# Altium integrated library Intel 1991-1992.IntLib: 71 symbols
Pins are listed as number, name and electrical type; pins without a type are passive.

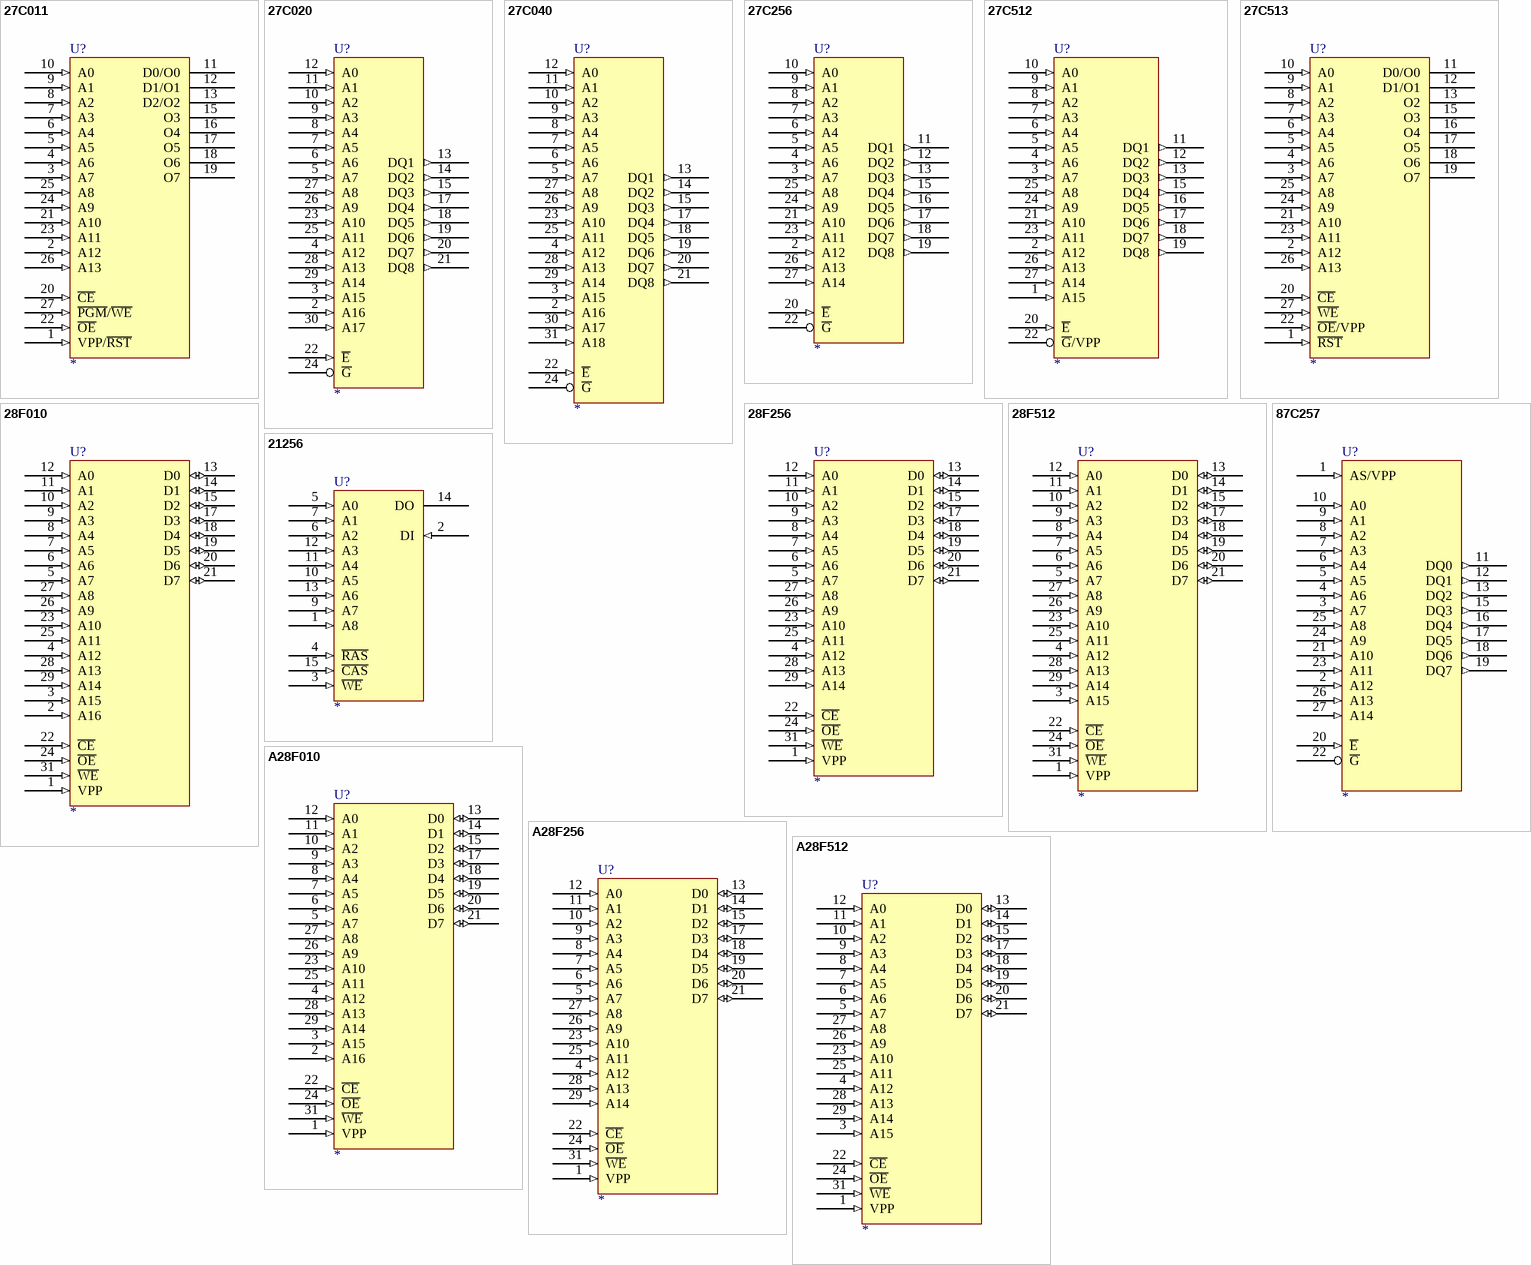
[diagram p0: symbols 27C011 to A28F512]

## 27C011
designator U?
pins: 1 VPP/~{RST} (in), 2 A12 (in), 3 A7 (in), 4 A6 (in), 5 A5 (in), 6 A4 (in), 7 A3 (in), 8 A2 (in), 9 A1 (in), 10 A0 (in), 11 D0/O0 (hiz), 12 D1/O1 (hiz), 13 D2/O2 (hiz), 14 GND (power) hidden to GND, 15 O3 (hiz), 16 O4 (hiz), 17 O5 (hiz), 18 O6 (hiz), 19 O7 (hiz), 20 ~{CE} (in), 21 A10 (in), 22 ~{OE} (in), 23 A11 (in), 24 A9 (in), 25 A8 (in), 26 A13 (in), 27 ~{PGM}/~{WE} (in), 28 VCC (power) hidden to VCC

## 27C020
designator U?
2 097 152-BIT UV ERASABLE PROGRAMMABLE READ-ONLY MEMORY
footprint DIP-32
pins: 1 VPP (power) hidden to VPP, 2 A16 (in), 3 A15 (in), 4 A12 (in), 5 A7 (in), 6 A6 (in), 7 A5 (in), 8 A4 (in), 9 A3 (in), 10 A2 (in), 11 A1 (in), 12 A0 (in), 13 DQ1 (out), 14 DQ2 (out), 15 DQ3 (out), 16 GND (power) hidden to GND, 17 DQ4 (out), 18 DQ5 (out), 19 DQ6 (out), 20 DQ7 (out), 21 DQ8 (out), 22 ~{E} (in), 23 A10 (in), 24 ~{G}, 25 A11 (in), 26 A9 (in), 27 A8 (in), 28 A13 (in), 29 A14 (in), 30 A17 (in), 32 VCC (power) hidden to VCC
1 alternate drawing of the same symbol

## 27C040
designator U?
4 194 304-BIT UV ERASABLE PROGRAMMABLE READ-ONLY MEMORY
footprint DIP-32
pins: 1 VPP (power) hidden to VPP, 2 A16 (in), 3 A15 (in), 4 A12 (in), 5 A7 (in), 6 A6 (in), 7 A5 (in), 8 A4 (in), 9 A3 (in), 10 A2 (in), 11 A1 (in), 12 A0 (in), 13 DQ1 (out), 14 DQ2 (out), 15 DQ3 (out), 16 GND (power) hidden to GND, 17 DQ4 (out), 18 DQ5 (out), 19 DQ6 (out), 20 DQ7 (out), 21 DQ8 (out), 22 ~{E} (in), 23 A10 (in), 24 ~{G}, 25 A11 (in), 26 A9 (in), 27 A8 (in), 28 A13 (in), 29 A14 (in), 30 A17 (in), 31 A18 (in), 32 VCC (power) hidden to VCC
1 alternate drawing of the same symbol

## 27C256
designator U?
262 144-BIT UV ERASABLE PROGRAMMABLE READ-ONLY MEMORY
footprint DIP-28
pins: 2 A12 (in), 3 A7 (in), 4 A6 (in), 5 A5 (in), 6 A4 (in), 7 A3 (in), 8 A2 (in), 9 A1 (in), 10 A0 (in), 11 DQ1 (out), 12 DQ2 (out), 13 DQ3 (out), 14 GND (power) hidden to GND, 15 DQ4 (out), 16 DQ5 (out), 17 DQ6 (out), 18 DQ7 (out), 19 DQ8 (out), 20 ~{E} (in), 21 A10 (in), 22 ~{G}, 23 A11 (in), 24 A9 (in), 25 A8 (in), 26 A13 (in), 27 A14 (in), 28 VCC (power) hidden to VCC
1 alternate drawing of the same symbol

## 27C512
designator U?
524 288-BIT ERASABLE UV PROGRAMMABLE READ-ONLY MEMORY
footprint DIP-28
pins: 1 A15 (in), 2 A12 (in), 3 A7 (in), 4 A6 (in), 5 A5 (in), 6 A4 (in), 7 A3 (in), 8 A2 (in), 9 A1 (in), 10 A0 (in), 11 DQ1 (out), 12 DQ2 (out), 13 DQ3 (out), 14 GND (power) hidden to GND, 15 DQ4 (out), 16 DQ5 (out), 17 DQ6 (out), 18 DQ7 (out), 19 DQ8 (out), 20 ~{E} (in), 21 A10 (in), 22 ~{G}/VPP, 23 A11 (in), 24 A9 (in), 25 A8 (in), 26 A13 (in), 27 A14 (in), 28 VCC (power) hidden to VCC
1 alternate drawing of the same symbol

## 27C513
designator U?
pins: 1 ~{RST} (in), 2 A12 (in), 3 A7 (in), 4 A6 (in), 5 A5 (in), 6 A4 (in), 7 A3 (in), 8 A2 (in), 9 A1 (in), 10 A0 (in), 11 D0/O0 (hiz), 12 D1/O1 (hiz), 13 O2 (hiz), 14 GND (power) hidden to GND, 15 O3 (hiz), 16 O4 (hiz), 17 O5 (hiz), 18 O6 (hiz), 19 O7 (hiz), 20 ~{CE} (in), 21 A10 (in), 22 ~{OE}/VPP (in), 23 A11 (in), 24 A9 (in), 25 A8 (in), 26 A13 (in), 27 ~{WE} (in), 28 VCC (power) hidden to VCC

## 28F010
designator U?
pins: 1 VPP (in), 2 A16 (in), 3 A15 (in), 4 A12 (in), 5 A7 (in), 6 A6 (in), 7 A5 (in), 8 A4 (in), 9 A3 (in), 10 A2 (in), 11 A1 (in), 12 A0 (in), 13 D0 (io), 14 D1 (io), 15 D2 (io), 16 GND (power) hidden to GND, 17 D3 (io), 18 D4 (io), 19 D5 (io), 20 D6 (io), 21 D7 (io), 22 ~{CE} (in), 23 A10 (in), 24 ~{OE} (in), 25 A11 (in), 26 A9 (in), 27 A8 (in), 28 A13 (in), 29 A14 (in), 31 ~{WE} (in), 32 VCC (power) hidden to VCC

## 28F256
designator U?
pins: 1 VPP (in), 4 A12 (in), 5 A7 (in), 6 A6 (in), 7 A5 (in), 8 A4 (in), 9 A3 (in), 10 A2 (in), 11 A1 (in), 12 A0 (in), 13 D0 (io), 14 D1 (io), 15 D2 (io), 16 VSS (power) hidden to VSS, 17 D3 (io), 18 D4 (io), 19 D5 (io), 20 D6 (io), 21 D7 (io), 22 ~{CE} (in), 23 A10 (in), 24 ~{OE} (in), 25 A11 (in), 26 A9 (in), 27 A8 (in), 28 A13 (in), 29 A14 (in), 31 ~{WE} (in), 32 VCC (power) hidden to VCC

## 28F512
designator U?
pins: 1 VPP (in), 3 A15 (in), 4 A12 (in), 5 A7 (in), 6 A6 (in), 7 A5 (in), 8 A4 (in), 9 A3 (in), 10 A2 (in), 11 A1 (in), 12 A0 (in), 13 D0 (io), 14 D1 (io), 15 D2 (io), 16 VSS (power) hidden to VSS, 17 D3 (io), 18 D4 (io), 19 D5 (io), 20 D6 (io), 21 D7 (io), 22 ~{CE} (in), 23 A10 (in), 24 ~{OE} (in), 25 A11 (in), 26 A9 (in), 27 A8 (in), 28 A13 (in), 29 A14 (in), 31 ~{WE} (in), 32 VCC (power) hidden to VCC

## 87C257
designator U?
262 144-BIT LATCHED UV ERASABLE PROGRAMMABLE READ-ONLY MEMORY
footprint DIP-28
pins: 1 AS/VPP (in), 2 A12 (in), 3 A7 (in), 4 A6 (in), 5 A5 (in), 6 A4 (in), 7 A3 (in), 8 A2 (in), 9 A1 (in), 10 A0 (in), 11 DQ0 (out), 12 DQ1 (out), 13 DQ2 (out), 14 GND (power) hidden to GND, 15 DQ3 (out), 16 DQ4 (out), 17 DQ5 (out), 18 DQ6 (out), 19 DQ7 (out), 20 ~{E} (in), 21 A10 (in), 22 ~{G}, 23 A11 (in), 24 A9 (in), 25 A8 (in), 26 A13 (in), 27 A14 (in), 28 VCC (power) hidden to VCC
1 alternate drawing of the same symbol

## 21256
designator U?
pins: 1 A8 (in), 2 DI (in), 3 ~{WE} (in), 4 ~{RAS} (in), 5 A0 (in), 6 A2 (in), 7 A1 (in), 8 VCC (power) hidden to VCC, 9 A7 (in), 10 A5 (in), 11 A4 (in), 12 A3 (in), 13 A6 (in), 14 DO (hiz), 15 ~{CAS} (in), 16 VSS (power) hidden to VSS

## A28F010
designator U?
pins: 1 VPP (in), 2 A16 (in), 3 A15 (in), 4 A12 (in), 5 A7 (in), 6 A6 (in), 7 A5 (in), 8 A4 (in), 9 A3 (in), 10 A2 (in), 11 A1 (in), 12 A0 (in), 13 D0 (io), 14 D1 (io), 15 D2 (io), 16 GND (power) hidden to GND, 17 D3 (io), 18 D4 (io), 19 D5 (io), 20 D6 (io), 21 D7 (io), 22 ~{CE} (in), 23 A10 (in), 24 ~{OE} (in), 25 A11 (in), 26 A9 (in), 27 A8 (in), 28 A13 (in), 29 A14 (in), 31 ~{WE} (in), 32 VCC (power) hidden to VCC

## A28F256
designator U?
pins: 1 VPP (in), 4 A12 (in), 5 A7 (in), 6 A6 (in), 7 A5 (in), 8 A4 (in), 9 A3 (in), 10 A2 (in), 11 A1 (in), 12 A0 (in), 13 D0 (io), 14 D1 (io), 15 D2 (io), 16 VSS (power) hidden to VSS, 17 D3 (io), 18 D4 (io), 19 D5 (io), 20 D6 (io), 21 D7 (io), 22 ~{CE} (in), 23 A10 (in), 24 ~{OE} (in), 25 A11 (in), 26 A9 (in), 27 A8 (in), 28 A13 (in), 29 A14 (in), 31 ~{WE} (in), 32 VCC (power) hidden to VCC

## A28F512
designator U?
pins: 1 VPP (in), 3 A15 (in), 4 A12 (in), 5 A7 (in), 6 A6 (in), 7 A5 (in), 8 A4 (in), 9 A3 (in), 10 A2 (in), 11 A1 (in), 12 A0 (in), 13 D0 (io), 14 D1 (io), 15 D2 (io), 16 VSS (power) hidden to VSS, 17 D3 (io), 18 D4 (io), 19 D5 (io), 20 D6 (io), 21 D7 (io), 22 ~{CE} (in), 23 A10 (in), 24 ~{OE} (in), 25 A11 (in), 26 A9 (in), 27 A8 (in), 28 A13 (in), 29 A14 (in), 31 ~{WE} (in), 32 VCC (power) hidden to VCC


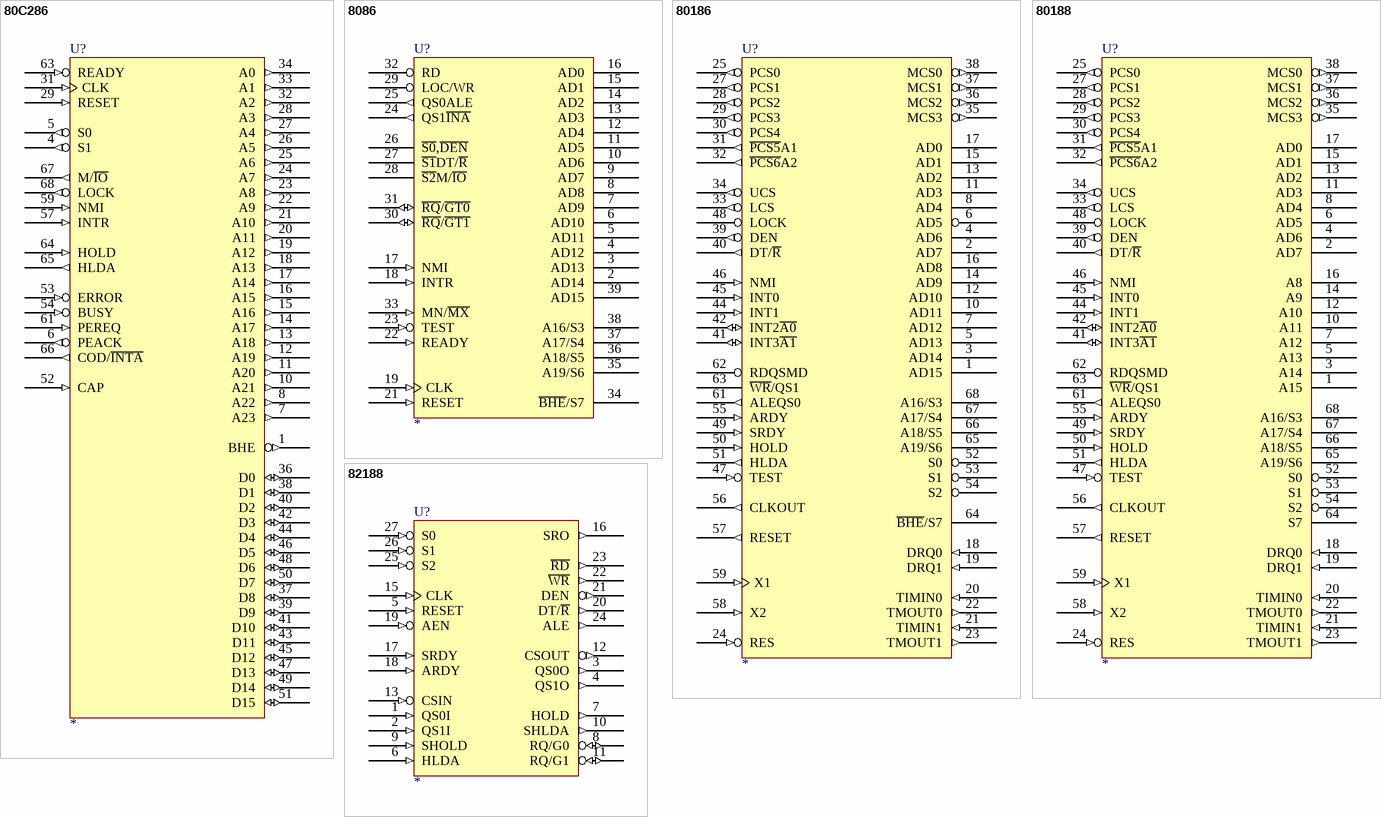
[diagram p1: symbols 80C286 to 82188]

## 80C286
designator U?
pins: 1 BHE (out), 4 S1 (out), 5 S0 (out), 6 PEACK (out), 7 A23 (out), 8 A22 (out), 9 VSS (power) hidden to VSS, 10 A21 (out), 11 A20 (out), 12 A19 (out), 13 A18 (out), 14 A17 (out), 15 A16 (out), 16 A15 (out), 17 A14 (out), 18 A13 (out), 19 A12 (out), 20 A11 (out), 21 A10 (out), 22 A9 (out), 23 A8 (out), 24 A7 (out), 25 A6 (out), 26 A5 (out), 27 A4 (out), 28 A3 (out), 29 RESET (in), 30 VCC (power) hidden to VCC, 31 CLK (in), 32 A2 (out), 33 A1 (out), 34 A0 (out), 35 VSS (power) hidden to VSS, 36 D0 (io), 37 D8 (io), 38 D1 (io), 39 D9 (io), 40 D2 (io), 41 D10 (io), 42 D3 (io), 43 D11 (io), 44 D4 (io), 45 D12 (io), 46 D5 (io), 47 D13 (io), 48 D6 (io), 49 D14 (io), 50 D7 (io), 51 D15 (io), 52 CAP (in), 53 ERROR (in), 54 BUSY (in), 57 INTR (in), 59 NMI (in), 60 VSS (power) hidden to VSS, 61 PEREQ (in), 62 VCC (power) hidden to VCC, 63 READY (in), 64 HOLD (in), 65 HLDA (out), 66 COD/~{INTA} (out), 67 M/~{IO} (out), 68 LOCK (out)

## 8086
designator U?
footprint DIP-40
pins: 1 GND (power) hidden to GND, 2 AD14 (hiz), 3 AD13 (hiz), 4 AD12 (hiz), 5 AD11 (hiz), 6 AD10 (hiz), 7 AD9 (hiz), 8 AD8 (hiz), 9 AD7 (hiz), 10 AD6 (hiz), 11 AD5 (hiz), 12 AD4 (hiz), 13 AD3 (hiz), 14 AD2 (hiz), 15 AD1 (hiz), 16 AD0 (hiz), 17 NMI (in), 18 INTR (in), 19 CLK (in), 20 GND (power) hidden to GND, 21 RESET (in), 22 READY (in), 23 TEST (in), 24 QS1~{INA} (out), 25 QS0ALE (out), 26 ~{S0},~{DEN} (hiz), 27 ~{S1}DT/~{R} (hiz), 28 ~{S2}M/~{IO} (hiz), 29 LOC/WR (hiz), 30 ~{RQ}/~{GT1} (io), 31 ~{RQ}/~{GT0} (io), 32 RD (hiz), 33 MN/~{MX} (in), 34 ~{BHE}/S7 (hiz), 35 A19/S6 (hiz), 36 A18/S5 (hiz), 37 A17/S4 (hiz), 38 A16/S3 (hiz), 39 AD15 (hiz), 40 VCC (power) hidden to VCC

## 80186
designator U?
footprint JEDECA-68
pins: 1 AD15 (hiz), 2 AD7 (hiz), 3 AD14 (hiz), 4 AD6 (hiz), 5 AD13 (hiz), 6 AD5 (hiz), 7 AD12 (hiz), 8 AD4 (hiz), 9 VCC (power) hidden to VCC, 10 AD11 (hiz), 11 AD3 (hiz), 12 AD10 (hiz), 13 AD2 (hiz), 14 AD9 (hiz), 15 AD1 (hiz), 16 AD8 (hiz), 17 AD0 (hiz), 18 DRQ0 (in), 19 DRQ1 (in), 20 TIMIN0 (in), 21 TIMIN1 (in), 22 TMOUT0 (out), 23 TMOUT1 (out), 24 RES (in), 25 PCS0 (out), 26 GND (power) hidden to GND, 27 PCS1 (out), 28 PCS2 (out), 29 PCS3 (out), 30 PCS4 (out), 31 ~{PCS5}A1 (out), 32 ~{PCS6}A2 (out), 33 LCS (out), 34 UCS (out), 35 MCS3 (out), 36 MCS2 (out), 37 MCS1 (out), 38 MCS0 (out), 39 DEN (out), 40 DT/~{R} (out), 41 INT3~{A1} (io), 42 INT2~{A0} (io), 43 VCC (power) hidden to VCC, 44 INT1 (in), 45 INT0 (in), 46 NMI (in), 47 TEST (in), 48 LOCK (hiz), 49 SRDY (in), 50 HOLD (in), 51 HLDA (out), 52 S0 (hiz), 53 S1 (hiz), 54 S2 (hiz), 55 ARDY (in), 56 CLKOUT (out), 57 RESET (out), 58 X2 (in), 59 X1 (in), 60 GND (power) hidden to GND, 61 ALEQS0 (out), 62 RDQSMD (hiz), 63 ~{WR}/QS1 (hiz), 64 ~{BHE}/S7 (hiz), 65 A19/S6 (hiz), 66 A18/S5 (hiz), 67 A17/S4 (hiz), 68 A16/S3 (hiz)

## 80188
designator U?
footprint JEDECA-68
pins: 1 A15 (hiz), 2 AD7 (hiz), 3 A14 (hiz), 4 AD6 (hiz), 5 A13 (hiz), 6 AD5 (hiz), 7 A12 (hiz), 8 AD4 (hiz), 9 VCC (power) hidden to VCC, 10 A11 (hiz), 11 AD3 (hiz), 12 A10 (hiz), 13 AD2 (hiz), 14 A9 (hiz), 15 AD1 (hiz), 16 A8 (hiz), 17 AD0 (hiz), 18 DRQ0 (in), 19 DRQ1 (in), 20 TIMIN0 (in), 21 TIMIN1 (in), 22 TMOUT0 (out), 23 TMOUT1 (out), 24 RES (in), 25 PCS0 (out), 26 GND (power) hidden to GND, 27 PCS1 (out), 28 PCS2 (out), 29 PCS3 (out), 30 PCS4 (out), 31 ~{PCS5}A1 (out), 32 ~{PCS6}A2 (out), 33 LCS (out), 34 UCS (out), 35 MCS3 (out), 36 MCS2 (out), 37 MCS1 (out), 38 MCS0 (out), 39 DEN (out), 40 DT/~{R} (out), 41 INT3~{A1} (io), 42 INT2~{A0} (io), 43 VCC (power) hidden to VCC, 44 INT1 (in), 45 INT0 (in), 46 NMI (in), 47 TEST (in), 48 LOCK (hiz), 49 SRDY (in), 50 HOLD (in), 51 HLDA (out), 52 S0 (hiz), 53 S1 (hiz), 54 S2 (hiz), 55 ARDY (in), 56 CLKOUT (out), 57 RESET (out), 58 X2 (in), 59 X1 (in), 60 GND (power) hidden to GND, 61 ALEQS0 (out), 62 RDQSMD (hiz), 63 ~{WR}/QS1 (hiz), 64 S7 (hiz), 65 A19/S6 (hiz), 66 A18/S5 (hiz), 67 A17/S4 (hiz), 68 A16/S3 (hiz)

## 82188
designator U?
pins: 1 QS0I (in), 2 QS1I (in), 3 QS0O (out), 4 QS1O (out), 5 RESET (in), 6 HLDA (in), 7 HOLD (out), 8 RQ/G0 (io), 9 SHOLD (in), 10 SHLDA (out), 11 RQ/G1 (io), 12 CSOUT (out), 13 CSIN (in), 14 VSS (power) hidden to VSS, 15 CLK (in), 16 SRO (out), 17 SRDY (in), 18 ARDY (in), 19 AEN (in), 20 DT/~{R} (out), 21 DEN (out), 22 ~{WR} (out), 23 ~{RD} (out), 24 ALE (out), 25 S2 (in), 26 S1 (in), 27 S0 (in), 28 VCC (power) hidden to VCC


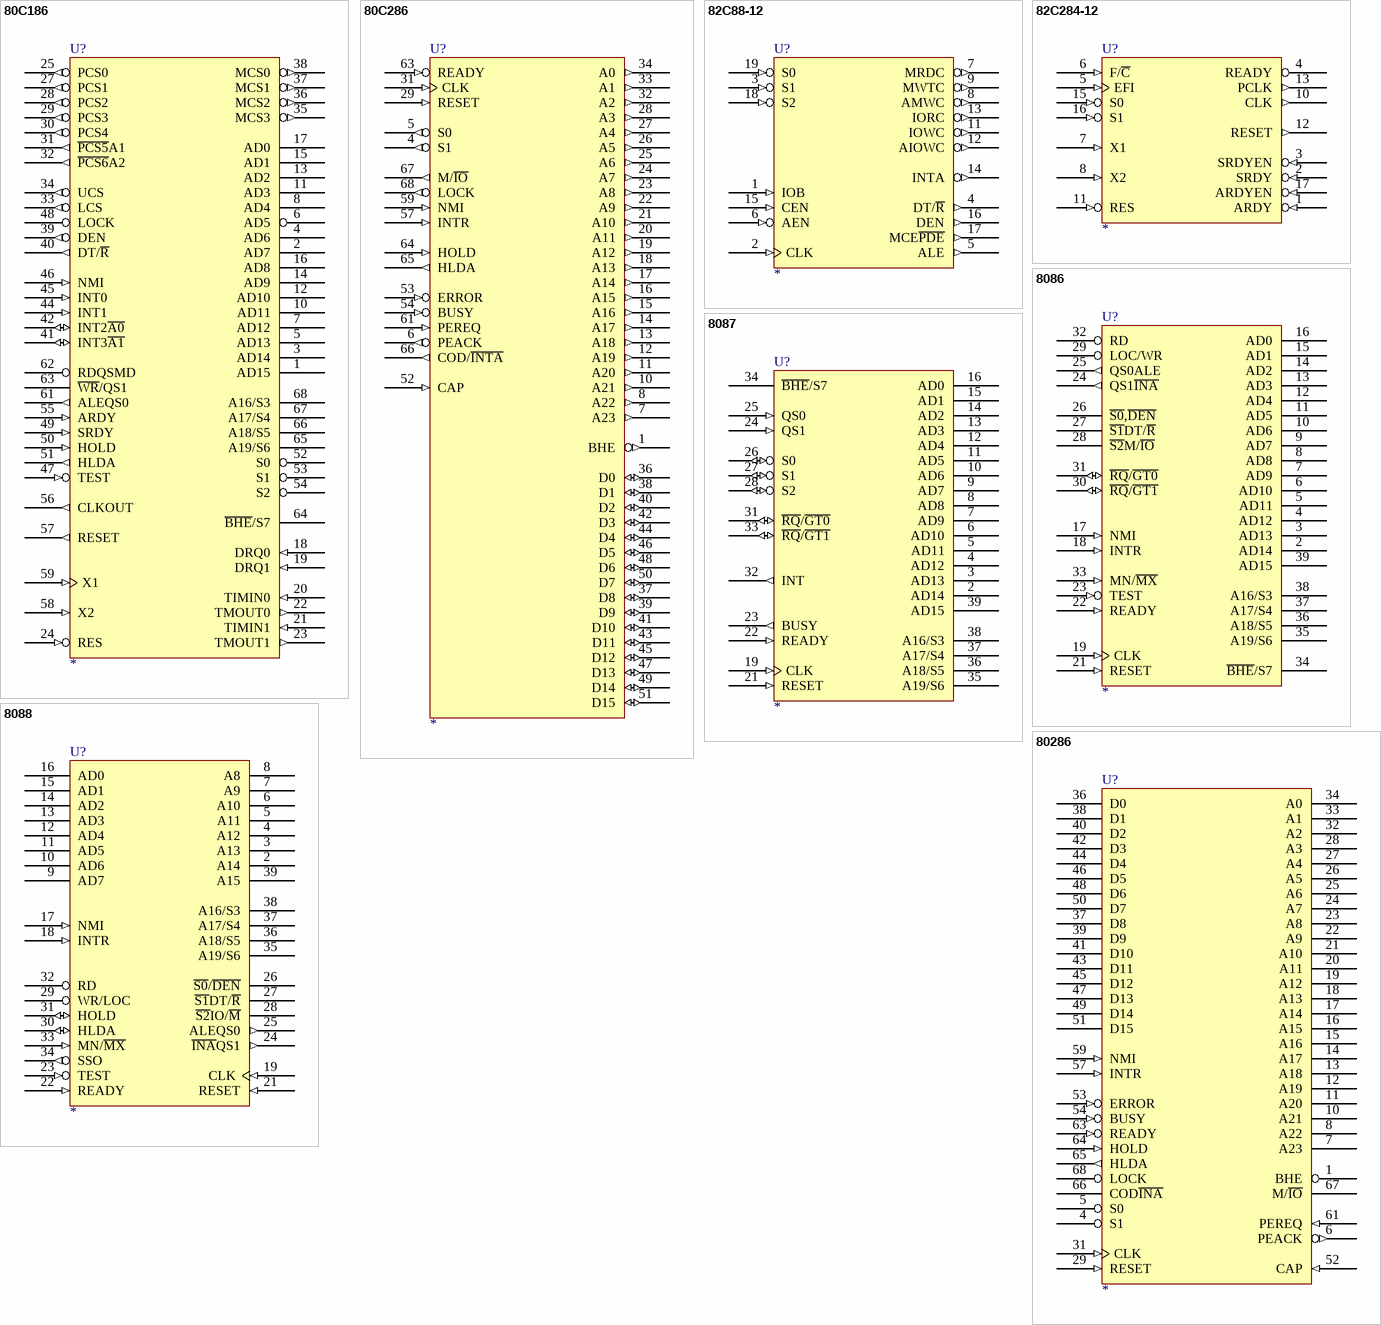
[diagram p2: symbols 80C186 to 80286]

## 80C186
designator U?
footprint JEDECA-68
pins: 1 AD15 (hiz), 2 AD7 (hiz), 3 AD14 (hiz), 4 AD6 (hiz), 5 AD13 (hiz), 6 AD5 (hiz), 7 AD12 (hiz), 8 AD4 (hiz), 9 VCC (power) hidden to VCC, 10 AD11 (hiz), 11 AD3 (hiz), 12 AD10 (hiz), 13 AD2 (hiz), 14 AD9 (hiz), 15 AD1 (hiz), 16 AD8 (hiz), 17 AD0 (hiz), 18 DRQ0 (in), 19 DRQ1 (in), 20 TIMIN0 (in), 21 TIMIN1 (in), 22 TMOUT0 (out), 23 TMOUT1 (out), 24 RES (in), 25 PCS0 (out), 26 GND (power) hidden to GND, 27 PCS1 (out), 28 PCS2 (out), 29 PCS3 (out), 30 PCS4 (out), 31 ~{PCS5}A1 (out), 32 ~{PCS6}A2 (out), 33 LCS (out), 34 UCS (out), 35 MCS3 (out), 36 MCS2 (out), 37 MCS1 (out), 38 MCS0 (out), 39 DEN (out), 40 DT/~{R} (out), 41 INT3~{A1} (io), 42 INT2~{A0} (io), 43 VCC (power) hidden to VCC, 44 INT1 (in), 45 INT0 (in), 46 NMI (in), 47 TEST (in), 48 LOCK (hiz), 49 SRDY (in), 50 HOLD (in), 51 HLDA (out), 52 S0 (hiz), 53 S1 (hiz), 54 S2 (hiz), 55 ARDY (in), 56 CLKOUT (out), 57 RESET (out), 58 X2 (in), 59 X1 (in), 60 GND (power) hidden to GND, 61 ALEQS0 (out), 62 RDQSMD (hiz), 63 ~{WR}/QS1 (hiz), 64 ~{BHE}/S7 (hiz), 65 A19/S6 (hiz), 66 A18/S5 (hiz), 67 A17/S4 (hiz), 68 A16/S3 (hiz)

## 80C286
designator U?
pins: 1 BHE (out), 4 S1 (out), 5 S0 (out), 6 PEACK (out), 7 A23 (out), 8 A22 (out), 9 VSS (power) hidden to VSS, 10 A21 (out), 11 A20 (out), 12 A19 (out), 13 A18 (out), 14 A17 (out), 15 A16 (out), 16 A15 (out), 17 A14 (out), 18 A13 (out), 19 A12 (out), 20 A11 (out), 21 A10 (out), 22 A9 (out), 23 A8 (out), 24 A7 (out), 25 A6 (out), 26 A5 (out), 27 A4 (out), 28 A3 (out), 29 RESET (in), 30 VCC (power) hidden to VCC, 31 CLK (in), 32 A2 (out), 33 A1 (out), 34 A0 (out), 35 VSS (power) hidden to VSS, 36 D0 (io), 37 D8 (io), 38 D1 (io), 39 D9 (io), 40 D2 (io), 41 D10 (io), 42 D3 (io), 43 D11 (io), 44 D4 (io), 45 D12 (io), 46 D5 (io), 47 D13 (io), 48 D6 (io), 49 D14 (io), 50 D7 (io), 51 D15 (io), 52 CAP (in), 53 ERROR (in), 54 BUSY (in), 57 INTR (in), 59 NMI (in), 60 VSS (power) hidden to VSS, 61 PEREQ (in), 62 VCC (power) hidden to VCC, 63 READY (in), 64 HOLD (in), 65 HLDA (out), 66 COD/~{INTA} (out), 67 M/~{IO} (out), 68 LOCK (out)

## 82C88-12
designator U?
footprint DIP-20
pins: 1 IOB (in), 2 CLK (in), 3 S1 (in), 4 DT/~{R} (out), 5 ALE (out), 6 AEN (in), 7 MRDC (out), 8 AMWC (out), 9 MWTC (out), 10 GND (power) hidden to GND, 11 IOWC (out), 12 AIOWC (out), 13 IORC (out), 14 INTA (out), 15 CEN (in), 16 DEN (out), 17 MCE~{PDE} (out), 18 S2 (in), 19 S0 (in), 20 VCC (power) hidden to VCC

## 82C284-12
designator U?
footprint DIP-18
pins: 1 ARDY (in), 2 SRDY (in), 3 SRDYEN (in), 4 READY (oc), 5 EFI (in), 6 F/~{C} (in), 7 X1 (in), 8 X2 (in), 9 GND (power) hidden to GND, 10 CLK (out), 11 RES (in), 12 RESET (out), 13 PCLK (out), 15 S0 (in), 16 S1 (in), 17 ARDYEN (in), 18 VCC (power) hidden to VCC

## 8086
designator U?
footprint DIP-40
pins: 1 GND (power) hidden to GND, 2 AD14 (hiz), 3 AD13 (hiz), 4 AD12 (hiz), 5 AD11 (hiz), 6 AD10 (hiz), 7 AD9 (hiz), 8 AD8 (hiz), 9 AD7 (hiz), 10 AD6 (hiz), 11 AD5 (hiz), 12 AD4 (hiz), 13 AD3 (hiz), 14 AD2 (hiz), 15 AD1 (hiz), 16 AD0 (hiz), 17 NMI (in), 18 INTR (in), 19 CLK (in), 20 GND (power) hidden to GND, 21 RESET (in), 22 READY (in), 23 TEST (in), 24 QS1~{INA} (out), 25 QS0ALE (out), 26 ~{S0},~{DEN} (hiz), 27 ~{S1}DT/~{R} (hiz), 28 ~{S2}M/~{IO} (hiz), 29 LOC/WR (hiz), 30 ~{RQ}/~{GT1} (io), 31 ~{RQ}/~{GT0} (io), 32 RD (hiz), 33 MN/~{MX} (in), 34 ~{BHE}/S7 (hiz), 35 A19/S6 (hiz), 36 A18/S5 (hiz), 37 A17/S4 (hiz), 38 A16/S3 (hiz), 39 AD15 (hiz), 40 VCC (power) hidden to VCC

## 8087
designator U?
footprint DIP-40
pins: 1 GND (power) hidden to GND, 2 AD14 (hiz), 3 AD13 (hiz), 4 AD12 (hiz), 5 AD11 (hiz), 6 AD10 (hiz), 7 AD9 (hiz), 8 AD8 (hiz), 9 AD7 (hiz), 10 AD6 (hiz), 11 AD5 (hiz), 12 AD4 (hiz), 13 AD3 (hiz), 14 AD2 (hiz), 15 AD1 (hiz), 16 AD0 (hiz), 19 CLK (in), 20 GND (power) hidden to GND, 21 RESET (in), 22 READY (in), 23 BUSY (out), 24 QS1 (in), 25 QS0 (in), 26 S0 (io), 27 S1 (io), 28 S2 (io), 31 ~{RQ}/~{GT0} (io), 32 INT (out), 33 ~{RQ}/~{GT1} (io), 34 ~{BHE}/S7 (hiz), 35 A19/S6 (hiz), 36 A18/S5 (hiz), 37 A17/S4 (hiz), 38 A16/S3 (hiz), 39 AD15 (hiz), 40 VCC (power) hidden to VCC

## 8088
designator U?
footprint DIP-40
pins: 1 GND (power) hidden to GND, 2 A14 (hiz), 3 A13 (hiz), 4 A12 (hiz), 5 A11 (hiz), 6 A10 (hiz), 7 A9 (hiz), 8 A8 (hiz), 9 AD7 (hiz), 10 AD6 (hiz), 11 AD5 (hiz), 12 AD4 (hiz), 13 AD3 (hiz), 14 AD2 (hiz), 15 AD1 (hiz), 16 AD0 (hiz), 17 NMI (in), 18 INTR (in), 19 CLK (in), 20 GND (power) hidden to GND, 21 RESET (in), 22 READY (in), 23 TEST (in), 24 ~{INA}QS1 (out), 25 ALEQS0 (out), 26 ~{S0}/~{DEN} (hiz), 27 ~{S1}DT/~{R} (hiz), 28 ~{S2}IO/~{M} (hiz), 29 WR/LOC (hiz), 30 HLDA (io), 31 HOLD (io), 32 RD (hiz), 33 MN/~{MX} (in), 34 SSO (out), 35 A19/S6 (hiz), 36 A18/S5 (hiz), 37 A17/S4 (hiz), 38 A16/S3 (hiz), 39 A15 (hiz), 40 VCC (power) hidden to VCC

## 80286
designator U?
footprint JEDECA-68
pins: 1 BHE (hiz), 4 S1 (hiz), 5 S0 (hiz), 6 PEACK (out), 7 A23 (hiz), 8 A22 (hiz), 9 GND (power) hidden to GND, 10 A21 (hiz), 11 A20 (hiz), 12 A19 (hiz), 13 A18 (hiz), 14 A17 (hiz), 15 A16 (hiz), 16 A15 (hiz), 17 A14 (hiz), 18 A13 (hiz), 19 A12 (hiz), 20 A11 (hiz), 21 A10 (hiz), 22 A9 (hiz), 23 A8 (hiz), 24 A7 (hiz), 25 A6 (hiz), 26 A5 (hiz), 27 A4 (hiz), 28 A3 (hiz), 29 RESET (in), 30 VCC (power) hidden to VCC, 31 CLK (in), 32 A2 (hiz), 33 A1 (hiz), 34 A0 (hiz), 35 GND (power) hidden to GND, 36 D0 (hiz), 37 D8 (hiz), 38 D1 (hiz), 39 D9 (hiz), 40 D2 (hiz), 41 D10 (hiz), 42 D3 (hiz), 43 D11 (hiz), 44 D4 (hiz), 45 D12 (hiz), 46 D5 (hiz), 47 D13 (hiz), 48 D6 (hiz), 49 D14 (hiz), 50 D7 (hiz), 51 D15 (hiz), 52 CAP (in), 53 ERROR (in), 54 BUSY (in), 57 INTR (in), 59 NMI (in), 60 GND (power) hidden to GND, 61 PEREQ (in), 62 VCC (power) hidden to VCC, 63 READY (in), 64 HOLD (in), 65 HLDA (out), 66 COD~{INA} (hiz), 67 M/~{IO} (hiz), 68 LOCK (hiz)


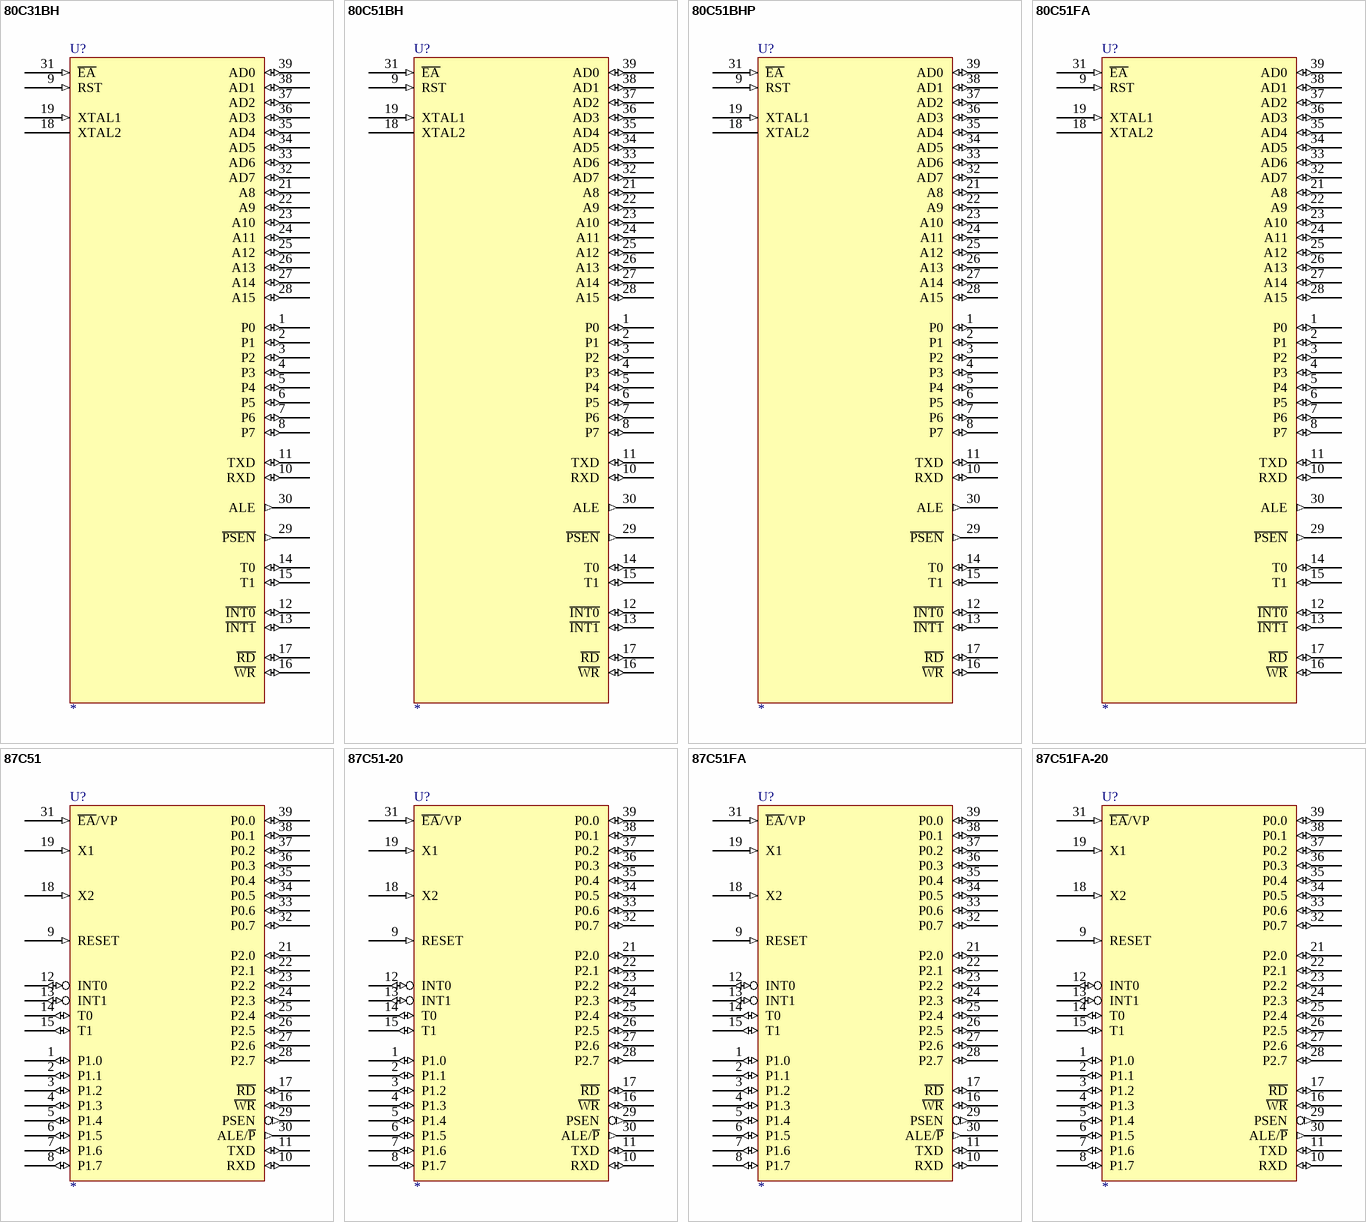
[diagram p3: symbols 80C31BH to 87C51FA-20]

## 80C31BH
designator U?
pins: 1 P0 (io), 2 P1 (io), 3 P2 (io), 4 P3 (io), 5 P4 (io), 6 P5 (io), 7 P6 (io), 8 P7 (io), 9 RST (in), 10 RXD (io), 11 TXD (io), 12 ~{INT0} (io), 13 ~{INT1} (io), 14 T0 (io), 15 T1 (io), 16 ~{WR} (io), 17 ~{RD} (io), 18 XTAL2, 19 XTAL1 (in), 20 VSS (power) hidden to VSS, 21 A8 (io), 22 A9 (io), 23 A10 (io), 24 A11 (io), 25 A12 (io), 26 A13 (io), 27 A14 (io), 28 A15 (io), 29 ~{PSEN} (out), 30 ALE (out), 31 ~{EA} (in), 32 AD7 (io), 33 AD6 (io), 34 AD5 (io), 35 AD4 (io), 36 AD3 (io), 37 AD2 (io), 38 AD1 (io), 39 AD0 (io), 40 VCC (power) hidden to VCC

## 80C51BH
designator U?
pins: 1 P0 (io), 2 P1 (io), 3 P2 (io), 4 P3 (io), 5 P4 (io), 6 P5 (io), 7 P6 (io), 8 P7 (io), 9 RST (in), 10 RXD (io), 11 TXD (io), 12 ~{INT0} (io), 13 ~{INT1} (io), 14 T0 (io), 15 T1 (io), 16 ~{WR} (io), 17 ~{RD} (io), 18 XTAL2, 19 XTAL1 (in), 20 VSS (power) hidden to VSS, 21 A8 (io), 22 A9 (io), 23 A10 (io), 24 A11 (io), 25 A12 (io), 26 A13 (io), 27 A14 (io), 28 A15 (io), 29 ~{PSEN} (out), 30 ALE (out), 31 ~{EA} (in), 32 AD7 (io), 33 AD6 (io), 34 AD5 (io), 35 AD4 (io), 36 AD3 (io), 37 AD2 (io), 38 AD1 (io), 39 AD0 (io), 40 VCC (power) hidden to VCC

## 80C51BHP
designator U?
pins: 1 P0 (io), 2 P1 (io), 3 P2 (io), 4 P3 (io), 5 P4 (io), 6 P5 (io), 7 P6 (io), 8 P7 (io), 9 RST (in), 10 RXD (io), 11 TXD (io), 12 ~{INT0} (io), 13 ~{INT1} (io), 14 T0 (io), 15 T1 (io), 16 ~{WR} (io), 17 ~{RD} (io), 18 XTAL2, 19 XTAL1 (in), 20 VSS (power) hidden to VSS, 21 A8 (io), 22 A9 (io), 23 A10 (io), 24 A11 (io), 25 A12 (io), 26 A13 (io), 27 A14 (io), 28 A15 (io), 29 ~{PSEN} (out), 30 ALE (out), 31 ~{EA} (in), 32 AD7 (io), 33 AD6 (io), 34 AD5 (io), 35 AD4 (io), 36 AD3 (io), 37 AD2 (io), 38 AD1 (io), 39 AD0 (io), 40 VCC (power) hidden to VCC

## 80C51FA
designator U?
pins: 1 P0 (io), 2 P1 (io), 3 P2 (io), 4 P3 (io), 5 P4 (io), 6 P5 (io), 7 P6 (io), 8 P7 (io), 9 RST (in), 10 RXD (io), 11 TXD (io), 12 ~{INT0} (io), 13 ~{INT1} (io), 14 T0 (io), 15 T1 (io), 16 ~{WR} (io), 17 ~{RD} (io), 18 XTAL2, 19 XTAL1 (in), 20 VSS (power) hidden to VSS, 21 A8 (io), 22 A9 (io), 23 A10 (io), 24 A11 (io), 25 A12 (io), 26 A13 (io), 27 A14 (io), 28 A15 (io), 29 ~{PSEN} (out), 30 ALE (out), 31 ~{EA} (in), 32 AD7 (io), 33 AD6 (io), 34 AD5 (io), 35 AD4 (io), 36 AD3 (io), 37 AD2 (io), 38 AD1 (io), 39 AD0 (io), 40 VCC (power) hidden to VCC

## 87C51
designator U?
pins: 1 P1.0 (io), 2 P1.1 (io), 3 P1.2 (io), 4 P1.3 (io), 5 P1.4 (io), 6 P1.5 (io), 7 P1.6 (io), 8 P1.7 (io), 9 RESET (in), 10 RXD (io), 11 TXD (io), 12 INT0 (io), 13 INT1 (io), 14 T0 (io), 15 T1 (io), 16 ~{WR} (io), 17 ~{RD} (io), 18 X2 (in), 19 X1 (in), 20 VSS (power) hidden to VSS, 21 P2.0 (io), 22 P2.1 (io), 23 P2.2 (io), 24 P2.3 (io), 25 P2.4 (io), 26 P2.5 (io), 27 P2.6 (io), 28 P2.7 (io), 29 PSEN (out), 30 ALE/~{P} (out), 31 ~{EA}/VP (in), 32 P0.7 (io), 33 P0.6 (io), 34 P0.5 (io), 35 P0.4 (io), 36 P0.3 (io), 37 P0.2 (io), 38 P0.1 (io), 39 P0.0 (io), 40 VCC (power) hidden to VCC

## 87C51-20
designator U?
pins: 1 P1.0 (io), 2 P1.1 (io), 3 P1.2 (io), 4 P1.3 (io), 5 P1.4 (io), 6 P1.5 (io), 7 P1.6 (io), 8 P1.7 (io), 9 RESET (in), 10 RXD (io), 11 TXD (io), 12 INT0 (io), 13 INT1 (io), 14 T0 (io), 15 T1 (io), 16 ~{WR} (io), 17 ~{RD} (io), 18 X2 (in), 19 X1 (in), 20 VSS (power) hidden to VSS, 21 P2.0 (io), 22 P2.1 (io), 23 P2.2 (io), 24 P2.3 (io), 25 P2.4 (io), 26 P2.5 (io), 27 P2.6 (io), 28 P2.7 (io), 29 PSEN (out), 30 ALE/~{P} (out), 31 ~{EA}/VP (in), 32 P0.7 (io), 33 P0.6 (io), 34 P0.5 (io), 35 P0.4 (io), 36 P0.3 (io), 37 P0.2 (io), 38 P0.1 (io), 39 P0.0 (io), 40 VCC (power) hidden to VCC

## 87C51FA
designator U?
pins: 1 P1.0 (io), 2 P1.1 (io), 3 P1.2 (io), 4 P1.3 (io), 5 P1.4 (io), 6 P1.5 (io), 7 P1.6 (io), 8 P1.7 (io), 9 RESET (in), 10 RXD (io), 11 TXD (io), 12 INT0 (io), 13 INT1 (io), 14 T0 (io), 15 T1 (io), 16 ~{WR} (io), 17 ~{RD} (io), 18 X2 (in), 19 X1 (in), 20 VSS (power) hidden to VSS, 21 P2.0 (io), 22 P2.1 (io), 23 P2.2 (io), 24 P2.3 (io), 25 P2.4 (io), 26 P2.5 (io), 27 P2.6 (io), 28 P2.7 (io), 29 PSEN (out), 30 ALE/~{P} (out), 31 ~{EA}/VP (in), 32 P0.7 (io), 33 P0.6 (io), 34 P0.5 (io), 35 P0.4 (io), 36 P0.3 (io), 37 P0.2 (io), 38 P0.1 (io), 39 P0.0 (io), 40 VCC (power) hidden to VCC

## 87C51FA-20
designator U?
pins: 1 P1.0 (io), 2 P1.1 (io), 3 P1.2 (io), 4 P1.3 (io), 5 P1.4 (io), 6 P1.5 (io), 7 P1.6 (io), 8 P1.7 (io), 9 RESET (in), 10 RXD (io), 11 TXD (io), 12 INT0 (io), 13 INT1 (io), 14 T0 (io), 15 T1 (io), 16 ~{WR} (io), 17 ~{RD} (io), 18 X2 (in), 19 X1 (in), 20 VSS (power) hidden to VSS, 21 P2.0 (io), 22 P2.1 (io), 23 P2.2 (io), 24 P2.3 (io), 25 P2.4 (io), 26 P2.5 (io), 27 P2.6 (io), 28 P2.7 (io), 29 PSEN (out), 30 ALE/~{P} (out), 31 ~{EA}/VP (in), 32 P0.7 (io), 33 P0.6 (io), 34 P0.5 (io), 35 P0.4 (io), 36 P0.3 (io), 37 P0.2 (io), 38 P0.1 (io), 39 P0.0 (io), 40 VCC (power) hidden to VCC

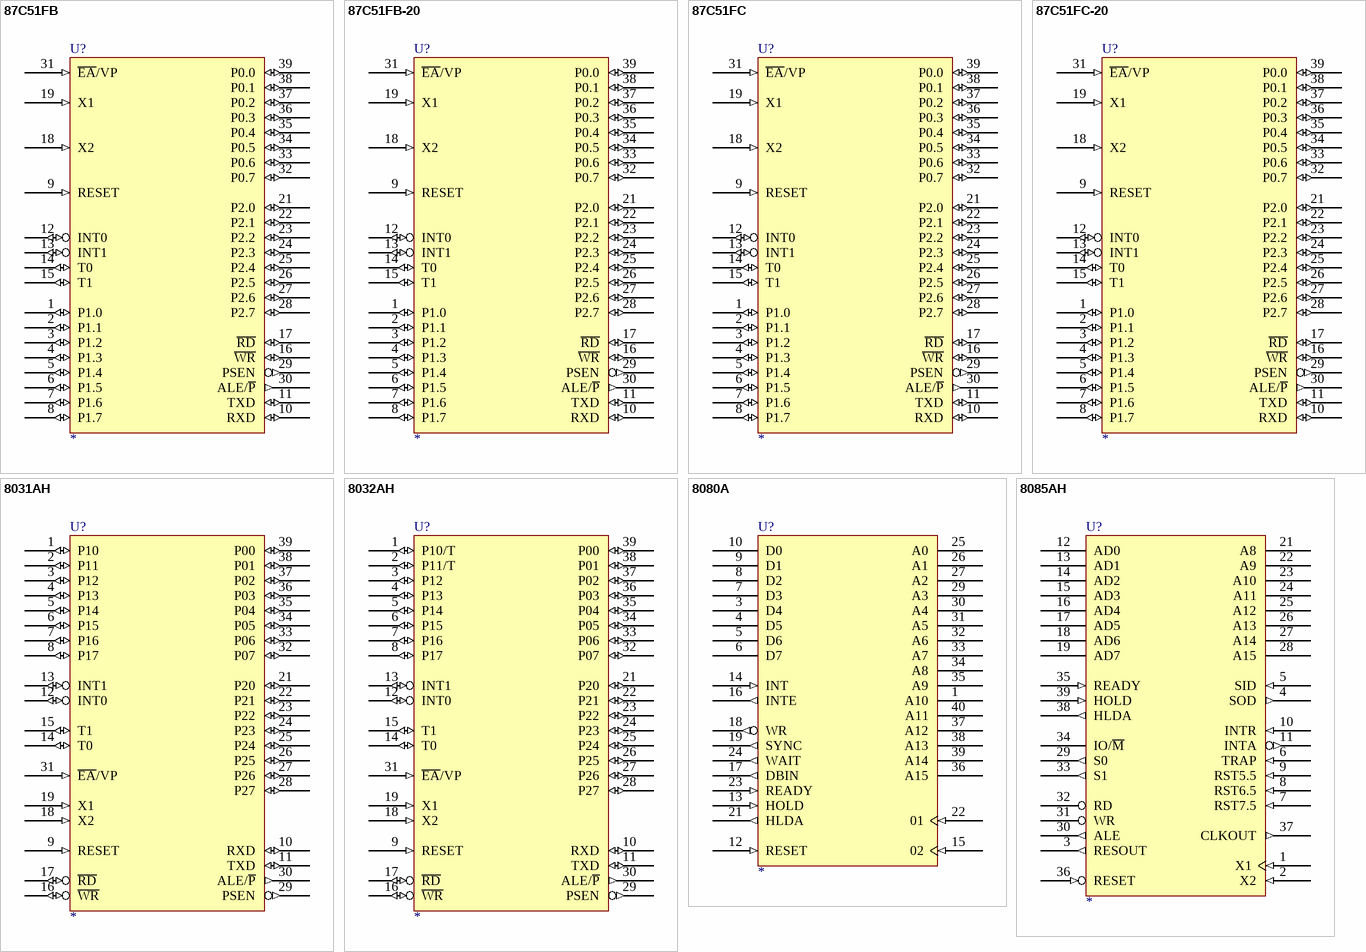
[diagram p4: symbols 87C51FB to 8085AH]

## 87C51FB
designator U?
pins: 1 P1.0 (io), 2 P1.1 (io), 3 P1.2 (io), 4 P1.3 (io), 5 P1.4 (io), 6 P1.5 (io), 7 P1.6 (io), 8 P1.7 (io), 9 RESET (in), 10 RXD (io), 11 TXD (io), 12 INT0 (io), 13 INT1 (io), 14 T0 (io), 15 T1 (io), 16 ~{WR} (io), 17 ~{RD} (io), 18 X2 (in), 19 X1 (in), 20 VSS (power) hidden to VSS, 21 P2.0 (io), 22 P2.1 (io), 23 P2.2 (io), 24 P2.3 (io), 25 P2.4 (io), 26 P2.5 (io), 27 P2.6 (io), 28 P2.7 (io), 29 PSEN (out), 30 ALE/~{P} (out), 31 ~{EA}/VP (in), 32 P0.7 (io), 33 P0.6 (io), 34 P0.5 (io), 35 P0.4 (io), 36 P0.3 (io), 37 P0.2 (io), 38 P0.1 (io), 39 P0.0 (io), 40 VCC (power) hidden to VCC

## 87C51FB-20
designator U?
pins: 1 P1.0 (io), 2 P1.1 (io), 3 P1.2 (io), 4 P1.3 (io), 5 P1.4 (io), 6 P1.5 (io), 7 P1.6 (io), 8 P1.7 (io), 9 RESET (in), 10 RXD (io), 11 TXD (io), 12 INT0 (io), 13 INT1 (io), 14 T0 (io), 15 T1 (io), 16 ~{WR} (io), 17 ~{RD} (io), 18 X2 (in), 19 X1 (in), 20 VSS (power) hidden to VSS, 21 P2.0 (io), 22 P2.1 (io), 23 P2.2 (io), 24 P2.3 (io), 25 P2.4 (io), 26 P2.5 (io), 27 P2.6 (io), 28 P2.7 (io), 29 PSEN (out), 30 ALE/~{P} (out), 31 ~{EA}/VP (in), 32 P0.7 (io), 33 P0.6 (io), 34 P0.5 (io), 35 P0.4 (io), 36 P0.3 (io), 37 P0.2 (io), 38 P0.1 (io), 39 P0.0 (io), 40 VCC (power) hidden to VCC

## 87C51FC
designator U?
pins: 1 P1.0 (io), 2 P1.1 (io), 3 P1.2 (io), 4 P1.3 (io), 5 P1.4 (io), 6 P1.5 (io), 7 P1.6 (io), 8 P1.7 (io), 9 RESET (in), 10 RXD (io), 11 TXD (io), 12 INT0 (io), 13 INT1 (io), 14 T0 (io), 15 T1 (io), 16 ~{WR} (io), 17 ~{RD} (io), 18 X2 (in), 19 X1 (in), 20 VSS (power) hidden to VSS, 21 P2.0 (io), 22 P2.1 (io), 23 P2.2 (io), 24 P2.3 (io), 25 P2.4 (io), 26 P2.5 (io), 27 P2.6 (io), 28 P2.7 (io), 29 PSEN (out), 30 ALE/~{P} (out), 31 ~{EA}/VP (in), 32 P0.7 (io), 33 P0.6 (io), 34 P0.5 (io), 35 P0.4 (io), 36 P0.3 (io), 37 P0.2 (io), 38 P0.1 (io), 39 P0.0 (io), 40 VCC (power) hidden to VCC

## 87C51FC-20
designator U?
pins: 1 P1.0 (io), 2 P1.1 (io), 3 P1.2 (io), 4 P1.3 (io), 5 P1.4 (io), 6 P1.5 (io), 7 P1.6 (io), 8 P1.7 (io), 9 RESET (in), 10 RXD (io), 11 TXD (io), 12 INT0 (io), 13 INT1 (io), 14 T0 (io), 15 T1 (io), 16 ~{WR} (io), 17 ~{RD} (io), 18 X2 (in), 19 X1 (in), 20 VSS (power) hidden to VSS, 21 P2.0 (io), 22 P2.1 (io), 23 P2.2 (io), 24 P2.3 (io), 25 P2.4 (io), 26 P2.5 (io), 27 P2.6 (io), 28 P2.7 (io), 29 PSEN (out), 30 ALE/~{P} (out), 31 ~{EA}/VP (in), 32 P0.7 (io), 33 P0.6 (io), 34 P0.5 (io), 35 P0.4 (io), 36 P0.3 (io), 37 P0.2 (io), 38 P0.1 (io), 39 P0.0 (io), 40 VCC (power) hidden to VCC

## 8031AH
designator U?
footprint DIP-40
pins: 1 P10 (io), 2 P11 (io), 3 P12 (io), 4 P13 (io), 5 P14 (io), 6 P15 (io), 7 P16 (io), 8 P17 (io), 9 RESET (in), 10 RXD (io), 11 TXD (io), 12 INT0 (io), 13 INT1 (io), 14 T0 (io), 15 T1 (io), 16 ~{WR} (io), 17 ~{RD} (io), 18 X2 (in), 19 X1 (in), 20 GND (power) hidden to GND, 21 P20 (io), 22 P21 (io), 23 P22 (io), 24 P23 (io), 25 P24 (io), 26 P25 (io), 27 P26 (io), 28 P27 (io), 29 PSEN (out), 30 ALE/~{P} (out), 31 ~{EA}/VP (in), 32 P07 (io), 33 P06 (io), 34 P05 (io), 35 P04 (io), 36 P03 (io), 37 P02 (io), 38 P01 (io), 39 P00 (io), 40 VCC (power) hidden to VCC

## 8032AH
designator U?
footprint DIP-40
pins: 1 P10/T (io), 2 P11/T (io), 3 P12 (io), 4 P13 (io), 5 P14 (io), 6 P15 (io), 7 P16 (io), 8 P17 (io), 9 RESET (in), 10 RXD (io), 11 TXD (io), 12 INT0 (io), 13 INT1 (io), 14 T0 (io), 15 T1 (io), 16 ~{WR} (io), 17 ~{RD} (io), 18 X2 (in), 19 X1 (in), 20 GND (power) hidden to GND, 21 P20 (io), 22 P21 (io), 23 P22 (io), 24 P23 (io), 25 P24 (io), 26 P25 (io), 27 P26 (io), 28 P27 (io), 29 PSEN (out), 30 ALE/~{P} (out), 31 ~{EA}/VP (in), 32 P07 (io), 33 P06 (io), 34 P05 (io), 35 P04 (io), 36 P03 (io), 37 P02 (io), 38 P01 (io), 39 P00 (io), 40 VCC (power) hidden to VCC

## 8080A
designator U?
footprint DIP-40
pins: 1 A10 (hiz), 2 GND (power) hidden to GND, 3 D4 (hiz), 4 D5 (hiz), 5 D6 (hiz), 6 D7 (hiz), 7 D3 (hiz), 8 D2 (hiz), 9 D1 (hiz), 10 D0 (hiz), 11 -5 (power) hidden to -5, 12 RESET (in), 13 HOLD (in), 14 INT (in), 15 02 (in), 16 INTE (out), 17 DBIN (out), 18 WR (out), 19 SYNC (out), 20 VCC (power) hidden to VCC, 21 HLDA (out), 22 01 (in), 23 READY (in), 24 WAIT (out), 25 A0 (hiz), 26 A1 (hiz), 27 A2 (hiz), 28 +12 (power) hidden to +12, 29 A3 (hiz), 30 A4 (hiz), 31 A5 (hiz), 32 A6 (hiz), 33 A7 (hiz), 34 A8 (hiz), 35 A9 (hiz), 36 A15 (hiz), 37 A12 (hiz), 38 A13 (hiz), 39 A14 (hiz), 40 A11 (hiz)

## 8085AH
designator U?
footprint DIP-40
pins: 1 X1 (in), 2 X2 (in), 3 RESOUT (out), 4 SOD (out), 5 SID (in), 6 TRAP (in), 7 RST7.5 (in), 8 RST6.5 (in), 9 RST5.5 (in), 10 INTR (in), 11 INTA (out), 12 AD0 (hiz), 13 AD1 (hiz), 14 AD2 (hiz), 15 AD3 (hiz), 16 AD4 (hiz), 17 AD5 (hiz), 18 AD6 (hiz), 19 AD7 (hiz), 20 GND (power) hidden to GND, 21 A8 (hiz), 22 A9 (hiz), 23 A10 (hiz), 24 A11 (hiz), 25 A12 (hiz), 26 A13 (hiz), 27 A14 (hiz), 28 A15 (hiz), 29 S0 (out), 30 ALE (out), 31 WR (hiz), 32 RD (hiz), 33 S1 (out), 34 IO/~{M} (hiz), 35 READY (in), 36 RESET (in), 37 CLKOUT (out), 38 HLDA (out), 39 HOLD (in), 40 VCC (power) hidden to VCC

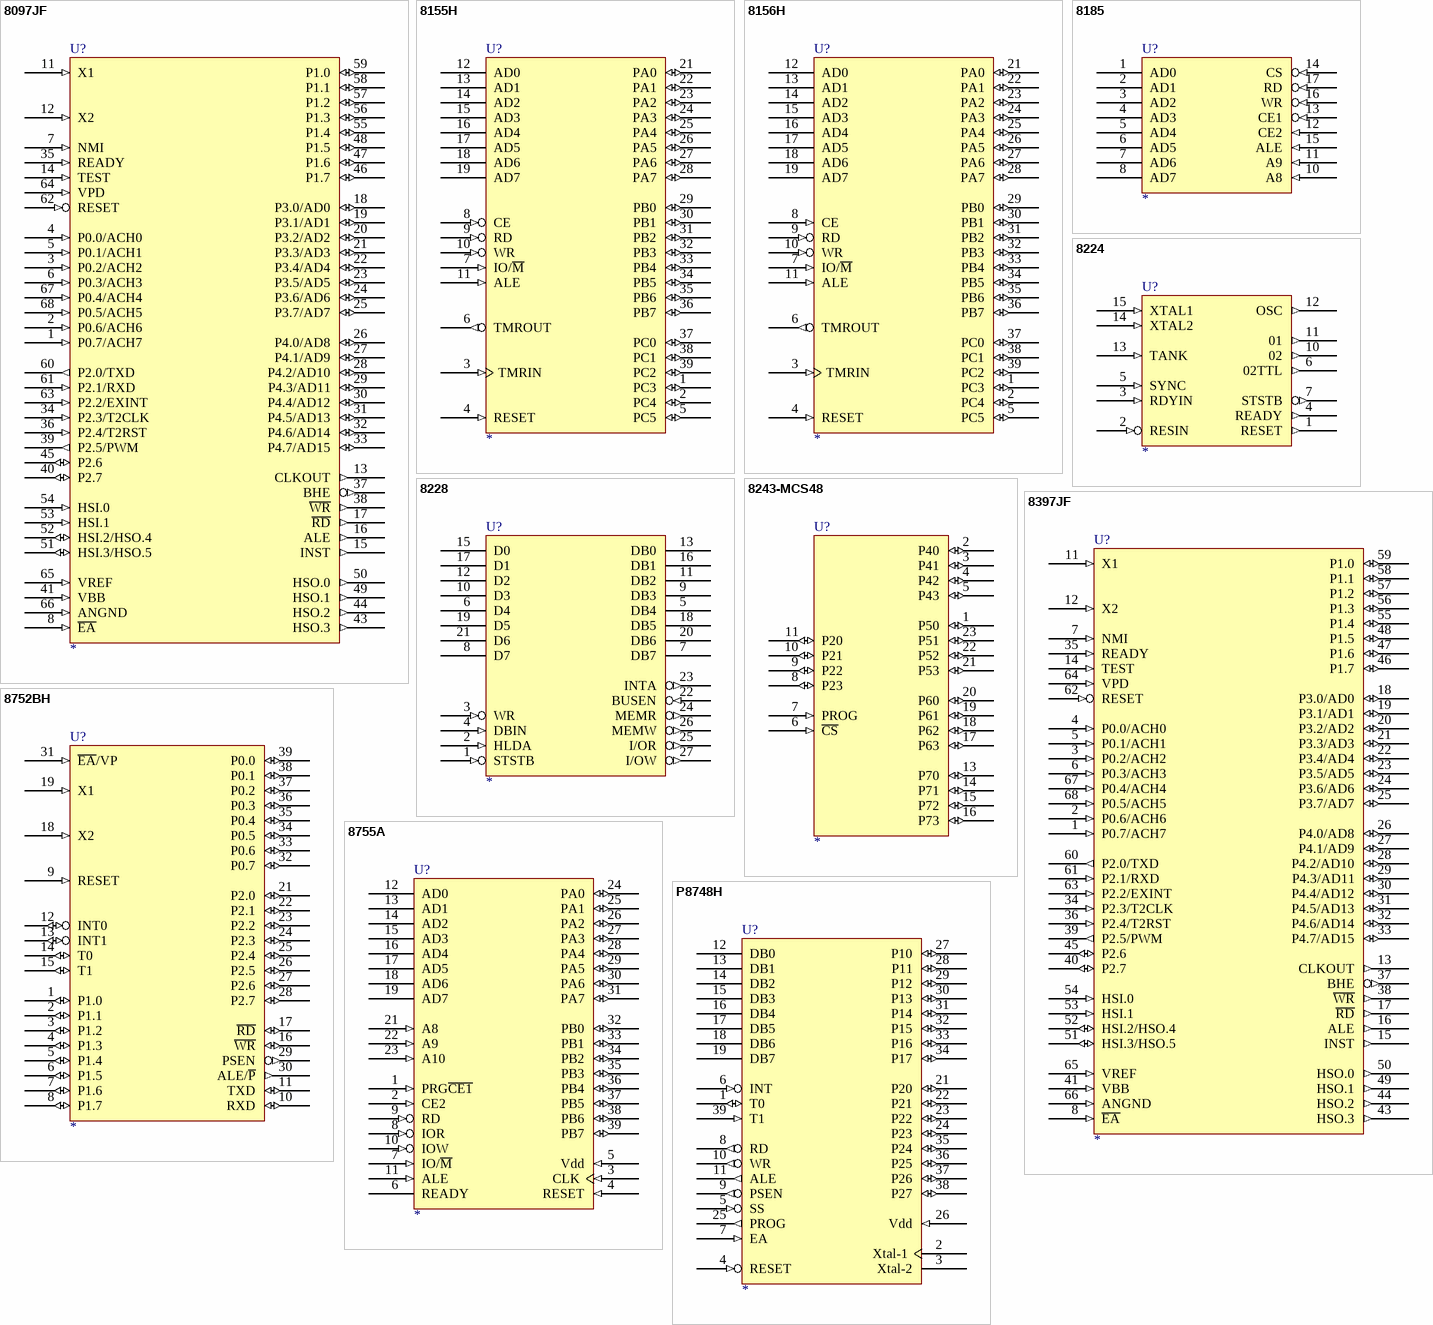
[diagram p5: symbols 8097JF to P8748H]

## 8097JF
designator U?
pins: 1 P0.7/ACH7 (in), 2 P0.6/ACH6 (in), 3 P0.2/ACH2 (in), 4 P0.0/ACH0 (in), 5 P0.1/ACH1 (in), 6 P0.3/ACH3 (in), 7 NMI (in), 8 ~{EA} (in), 9 VCC (power) hidden to VCC, 10 VSS (power) hidden to VSS, 11 X1 (in), 12 X2 (in), 13 CLKOUT (out), 14 TEST (in), 15 INST (out), 16 ALE (out), 17 ~{RD} (out), 18 P3.0/AD0 (io), 19 P3.1/AD1 (io), 20 P3.2/AD2 (io), 21 P3.3/AD3 (io), 22 P3.4/AD4 (io), 23 P3.5/AD5 (io), 24 P3.6/AD6 (io), 25 P3.7/AD7 (io), 26 P4.0/AD8 (io), 27 P4.1/AD9 (io), 28 P4.2/AD10 (io), 29 P4.3/AD11 (io), 30 P4.4/AD12 (io), 31 P4.5/AD13 (io), 32 P4.6/AD14 (io), 33 P4.7/AD15 (io), 34 P2.3/T2CLK (in), 35 READY (in), 36 P2.4/T2RST (in), 37 BHE (out), 38 ~{WR} (out), 39 P2.5/PWM (out), 40 P2.7 (io), 41 VBB (in), 42 VSS (power) hidden to VSS, 43 HSO.3 (out), 44 HSO.2 (out), 45 P2.6 (io), 46 P1.7 (io), 47 P1.6 (io), 48 P1.5 (io), 49 HSO.1 (out), 50 HSO.0 (out), 51 HSI.3/HSO.5 (io), 52 HSI.2/HSO.4 (io), 53 HSI.1 (in), 54 HSI.0 (in), 55 P1.4 (io), 56 P1.3 (io), 57 P1.2 (io), 58 P1.1 (io), 59 P1.0 (io), 60 P2.0/TXD (out), 61 P2.1/RXD (in), 62 RESET (in), 63 P2.2/EXINT (in), 64 VPD (in), 65 VREF (in), 66 ANGND (in), 67 P0.4/ACH4 (in), 68 P0.5/ACH5 (in)

## 8155H
designator U?
footprint DIP-40
pins: 1 PC3 (io), 2 PC4 (io), 3 TMRIN (in), 4 RESET (in), 5 PC5 (io), 6 TMROUT (out), 7 IO/~{M} (in), 8 CE (in), 9 RD (in), 10 WR (in), 11 ALE (in), 12 AD0 (hiz), 13 AD1 (hiz), 14 AD2 (hiz), 15 AD3 (hiz), 16 AD4 (hiz), 17 AD5 (hiz), 18 AD6 (hiz), 19 AD7 (hiz), 20 GND (power) hidden to GND, 21 PA0 (io), 22 PA1 (io), 23 PA2 (io), 24 PA3 (io), 25 PA4 (io), 26 PA5 (io), 27 PA6 (io), 28 PA7 (io), 29 PB0 (io), 30 PB1 (io), 31 PB2 (io), 32 PB3 (io), 33 PB4 (io), 34 PB5 (io), 35 PB6 (io), 36 PB7 (io), 37 PC0 (io), 38 PC1 (io), 39 PC2 (io), 40 VCC (power) hidden to VCC

## 8156H
designator U?
footprint DIP-40
pins: 1 PC3 (io), 2 PC4 (io), 3 TMRIN (in), 4 RESET (in), 5 PC5 (io), 6 TMROUT (out), 7 IO/~{M} (in), 8 CE (in), 9 RD (in), 10 WR (in), 11 ALE (in), 12 AD0 (hiz), 13 AD1 (hiz), 14 AD2 (hiz), 15 AD3 (hiz), 16 AD4 (hiz), 17 AD5 (hiz), 18 AD6 (hiz), 19 AD7 (hiz), 20 GND (power) hidden to GND, 21 PA0 (io), 22 PA1 (io), 23 PA2 (io), 24 PA3 (io), 25 PA4 (io), 26 PA5 (io), 27 PA6 (io), 28 PA7 (io), 29 PB0 (io), 30 PB1 (io), 31 PB2 (io), 32 PB3 (io), 33 PB4 (io), 34 PB5 (io), 35 PB6 (io), 36 PB7 (io), 37 PC0 (io), 38 PC1 (io), 39 PC2 (io), 40 VCC (power) hidden to VCC

## 8185
designator U?
footprint DIP-18
pins: 1 AD0 (hiz), 2 AD1 (hiz), 3 AD2 (hiz), 4 AD3 (hiz), 5 AD4 (hiz), 6 AD5 (hiz), 7 AD6 (hiz), 8 AD7 (hiz), 9 GND (power) hidden to GND, 10 A8 (in), 11 A9 (in), 12 CE2 (in), 13 CE1 (in), 14 CS (in), 15 ALE (in), 16 WR (in), 17 RD (in), 18 VCC (power) hidden to VCC

## 8224
designator U?
footprint DIP-16
pins: 1 RESET (out), 2 RESIN (in), 3 RDYIN (in), 4 READY (out), 5 SYNC (in), 6 02TTL (out), 7 STSTB (out), 8 GND (power) hidden to GND, 9 VDD (power) hidden to VDD, 10 02 (out), 11 01 (out), 12 OSC (out), 13 TANK (in), 14 XTAL2 (in), 15 XTAL1 (in), 16 VCC (power) hidden to VCC

## 8228
designator U?
footprint DIP-28
pins: 1 STSTB (in), 2 HLDA (in), 3 WR (in), 4 DBIN (in), 5 DB4 (hiz), 6 D4 (hiz), 7 DB7 (hiz), 8 D7 (hiz), 9 DB3 (hiz), 10 D3 (hiz), 11 DB2 (hiz), 12 D2 (hiz), 13 DB0 (hiz), 14 GND (power) hidden to GND, 15 D0 (hiz), 16 DB1 (hiz), 17 D1 (hiz), 18 DB5 (hiz), 19 D5 (hiz), 20 DB6 (hiz), 21 D6 (hiz), 22 BUSEN (in), 23 INTA (out), 24 MEMR (out), 25 I/OR (out), 26 MEMW (out), 27 I/OW (out), 28 VCC (power) hidden to VCC

## 8243-MCS48
designator U?
pins: 1 P50 (io), 2 P40 (io), 3 P41 (io), 4 P42 (io), 5 P43 (io), 6 ~{CS} (in), 7 PROG (in), 8 P23 (io), 9 P22 (io), 10 P21 (io), 11 P20 (io), 12 GND (power) hidden to GND, 13 P70 (io), 14 P71 (io), 15 P72 (io), 16 P73 (io), 17 P63 (io), 18 P62 (io), 19 P61 (io), 20 P60 (io), 21 P53 (io), 22 P52 (io), 23 P51 (io), 24 VCC (power) hidden to VCC

## 8397JF
designator U?
pins: 1 P0.7/ACH7 (in), 2 P0.6/ACH6 (in), 3 P0.2/ACH2 (in), 4 P0.0/ACH0 (in), 5 P0.1/ACH1 (in), 6 P0.3/ACH3 (in), 7 NMI (in), 8 ~{EA} (in), 9 VCC (power) hidden to VCC, 10 VSS (power) hidden to VSS, 11 X1 (in), 12 X2 (in), 13 CLKOUT (out), 14 TEST (in), 15 INST (out), 16 ALE (out), 17 ~{RD} (out), 18 P3.0/AD0 (io), 19 P3.1/AD1 (io), 20 P3.2/AD2 (io), 21 P3.3/AD3 (io), 22 P3.4/AD4 (io), 23 P3.5/AD5 (io), 24 P3.6/AD6 (io), 25 P3.7/AD7 (io), 26 P4.0/AD8 (io), 27 P4.1/AD9 (io), 28 P4.2/AD10 (io), 29 P4.3/AD11 (io), 30 P4.4/AD12 (io), 31 P4.5/AD13 (io), 32 P4.6/AD14 (io), 33 P4.7/AD15 (io), 34 P2.3/T2CLK (in), 35 READY (in), 36 P2.4/T2RST (in), 37 BHE (out), 38 ~{WR} (out), 39 P2.5/PWM (out), 40 P2.7 (io), 41 VBB (in), 42 VSS (power) hidden to VSS, 43 HSO.3 (out), 44 HSO.2 (out), 45 P2.6 (io), 46 P1.7 (io), 47 P1.6 (io), 48 P1.5 (io), 49 HSO.1 (out), 50 HSO.0 (out), 51 HSI.3/HSO.5 (io), 52 HSI.2/HSO.4 (io), 53 HSI.1 (in), 54 HSI.0 (in), 55 P1.4 (io), 56 P1.3 (io), 57 P1.2 (io), 58 P1.1 (io), 59 P1.0 (io), 60 P2.0/TXD (out), 61 P2.1/RXD (in), 62 RESET (in), 63 P2.2/EXINT (in), 64 VPD (in), 65 VREF (in), 66 ANGND (in), 67 P0.4/ACH4 (in), 68 P0.5/ACH5 (in)

## 8752BH
designator U?
pins: 1 P1.0 (io), 2 P1.1 (io), 3 P1.2 (io), 4 P1.3 (io), 5 P1.4 (io), 6 P1.5 (io), 7 P1.6 (io), 8 P1.7 (io), 9 RESET (in), 10 RXD (io), 11 TXD (io), 12 INT0 (io), 13 INT1 (io), 14 T0 (io), 15 T1 (io), 16 ~{WR} (io), 17 ~{RD} (io), 18 X2 (in), 19 X1 (in), 20 VSS (power) hidden to VSS, 21 P2.0 (io), 22 P2.1 (io), 23 P2.2 (io), 24 P2.3 (io), 25 P2.4 (io), 26 P2.5 (io), 27 P2.6 (io), 28 P2.7 (io), 29 PSEN (out), 30 ALE/~{P} (out), 31 ~{EA}/VP (in), 32 P0.7 (io), 33 P0.6 (io), 34 P0.5 (io), 35 P0.4 (io), 36 P0.3 (io), 37 P0.2 (io), 38 P0.1 (io), 39 P0.0 (io), 40 VCC (power) hidden to VCC

## 8755A
designator U?
footprint DIP-40
pins: 1 PRG~{CE1} (in), 2 CE2 (in), 3 CLK (in), 4 RESET (in), 5 Vdd (in), 6 READY (hiz), 7 IO/~{M} (in), 8 IOR (in), 9 RD (in), 10 IOW (in), 11 ALE (in), 12 AD0 (hiz), 13 AD1 (hiz), 14 AD2 (hiz), 15 AD3 (hiz), 16 AD4 (hiz), 17 AD5 (hiz), 18 AD6 (hiz), 19 AD7 (hiz), 20 GND (power) hidden to GND, 21 A8 (in), 22 A9 (in), 23 A10 (in), 24 PA0 (io), 25 PA1 (io), 26 PA2 (io), 27 PA3 (io), 28 PA4 (io), 29 PA5 (io), 30 PA6 (io), 31 PA7 (io), 32 PB0 (io), 33 PB1 (io), 34 PB2 (io), 35 PB3 (io), 36 PB4 (io), 37 PB5 (io), 38 PB6 (io), 39 PB7 (io), 40 VCC (power) hidden to VCC

## P8748H
designator U?
footprint DIP-40
pins: 1 T0 (io), 2 Xtal-1, 3 Xtal-2, 4 RESET (in), 5 SS (in), 6 INT (in), 7 EA (in), 8 RD (out), 9 PSEN (out), 10 WR (out), 11 ALE (out), 12 DB0 (hiz), 13 DB1 (hiz), 14 DB2 (hiz), 15 DB3 (hiz), 16 DB4 (hiz), 17 DB5 (hiz), 18 DB6 (hiz), 19 DB7 (hiz), 20 GND (power) hidden to GND, 21 P20 (io), 22 P21 (io), 23 P22 (io), 24 P23 (io), 25 PROG (out), 26 Vdd (in), 27 P10 (io), 28 P11 (io), 29 P12 (io), 30 P13 (io), 31 P14 (io), 32 P15 (io), 33 P16 (io), 34 P17 (io), 35 P24 (io), 36 P25 (io), 37 P26 (io), 38 P27 (io), 39 T1 (in), 40 VCC (power) hidden to VCC


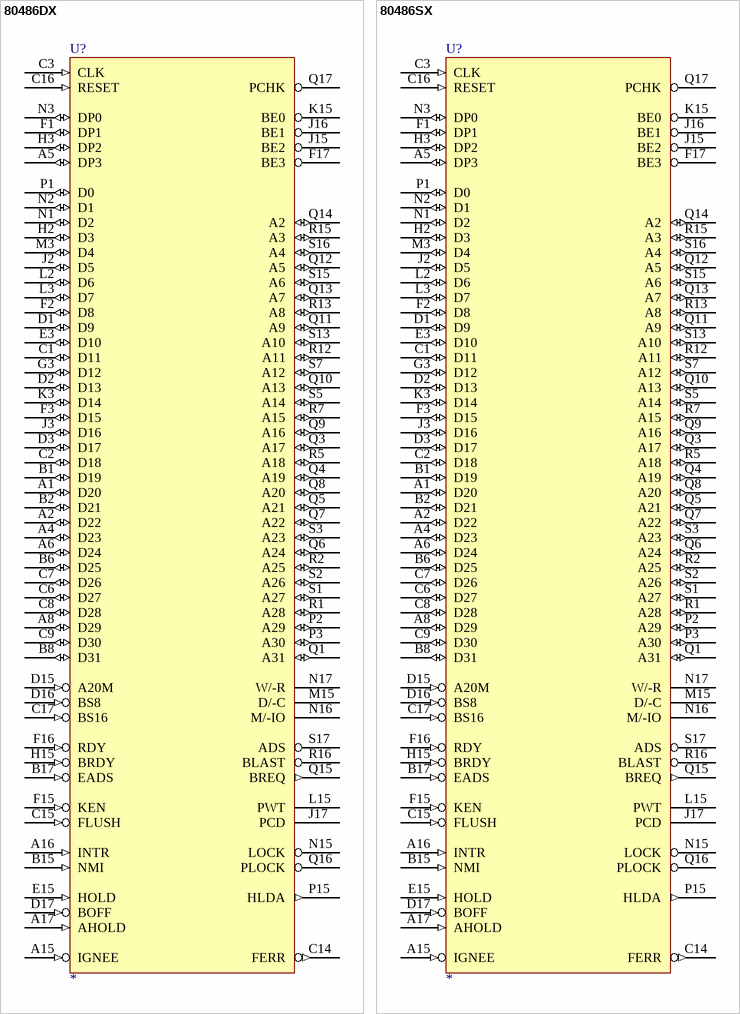
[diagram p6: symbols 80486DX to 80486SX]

## 80486DX
designator U?
pins: A1 D20 (io), A2 D22 (io), A4 D23 (io), A5 DP3 (io), A6 D24 (io), A7 GND (power) hidden to GND, A8 D29 (io), A9 GND (power) hidden to GND, A11 GND (power) hidden to GND, A15 IGNEE (in), A16 INTR (in), A17 AHOLD (in), B1 D19 (io), B2 D21 (io), B3 GND (power) hidden to GND, B4 GND (power) hidden to GND, B5 GND (power) hidden to GND, B6 D25 (io), B7 VCC (power) hidden to VCC, B8 D31 (io), B9 VCC (power) hidden to VCC, B11 VCC (power) hidden to VCC, B15 NMI (in), B17 EADS (in), C1 D11 (io), C2 D18 (io), C3 CLK (in), C4 VCC (power) hidden to VCC, C5 VCC (power) hidden to VCC, C6 D27 (io), C7 D26 (io), C8 D28 (io), C9 D30 (io), C14 FERR (out), C15 FLUSH (in), C16 RESET (in), C17 BS16 (in), D1 D9 (io), D2 D13 (io), D3 D17 (io), D15 A20M (in), D16 BS8 (in), D17 BOFF (in), E1 GND (power) hidden to GND, E2 VCC (power) hidden to VCC, E3 D10 (io), E15 HOLD (in), E16 VCC (power) hidden to VCC, E17 GND (power) hidden to GND, F1 DP1 (io), F2 D8 (io), F3 D15 (io), F15 KEN (in), F16 RDY (in), F17 BE3 (hiz), G1 GND (power) hidden to GND, G2 VCC (power) hidden to VCC, G3 D12 (io), G16 VCC (power) hidden to VCC, G17 GND (power) hidden to GND, H1 GND (power) hidden to GND, H2 D3 (io), H3 DP2 (io), H15 BRDY (in), H16 VCC (power) hidden to VCC, H17 GND (power) hidden to GND, J1 VCC (power) hidden to VCC, J2 D5 (io), J3 D16 (io), J15 BE2 (hiz), J16 BE1 (hiz), J17 PCD (hiz), K1 GND (power) hidden to GND, K2 VCC (power) hidden to VCC, K3 D14 (io), K15 BE0 (hiz), K16 VCC (power) hidden to VCC, K17 GND (power) hidden to GND, L1 GND (power) hidden to GND, L2 D6 (io), L3 D7 (io), L15 PWT (hiz), L16 VCC (power) hidden to VCC, M1 GND (power) hidden to GND, M2 VCC (power) hidden to VCC, M3 D4 (io), M15 D/-C (hiz), M16 VCC (power) hidden to VCC, M17 GND (power) hidden to GND, N1 D2 (io), N2 D1 (io), N3 DP0 (io), N15 LOCK (hiz), N16 M/-IO (hiz), N17 W/-R (hiz), P1 D0 (io), P2 A29 (io), P3 A30 (io), P15 HLDA (out), P16 VCC (power) hidden to VCC, P17 GND (power) hidden to GND, Q1 A31 (io), Q2 GND (power) hidden to GND, Q3 A17 (io), Q4 A19 (io), Q5 A21 (io), Q6 A24 (io), Q7 A22 (io), Q8 A20 (io), Q9 A16 (io), Q10 A13 (io), Q11 A9 (io), Q12 A5 (io), Q13 A7 (io), Q14 A2 (io), Q15 BREQ (out), Q16 PLOCK (hiz), Q17 PCHK (hiz), R1 A28 (io), R2 A25 (io), R3 VCC (power) hidden to VCC, R4 GND (power) hidden to GND, R5 A18 (io), R6 VCC (power) hidden to VCC, R7 A15 (io), R8 VCC (power) hidden to VCC, R9 VCC (power) hidden to VCC, R10 VCC (power) hidden to VCC, R11 VCC (power) hidden to VCC, R12 A11 (io), R13 A8 (io), R14 VCC (power) hidden to VCC, R15 A3 (io), R16 BLAST (hiz), S1 A27 (io), S2 A26 (io), S3 A23 (io), S5 A14 (io), S6 GND (power) hidden to GND, S7 A12 (io), S8 GND (power) hidden to GND, S9 GND (power) hidden to GND, S10 GND (power) hidden to GND, S11 GND (power) hidden to GND, S12 GND (power) hidden to GND, S13 A10 (io), S14 GND (power) hidden to GND, S15 A6 (io), S16 A4 (io), S17 ADS (hiz)

## 80486SX
designator U?
pins: A1 D20 (io), A2 D22 (io), A4 D23 (io), A5 DP3 (io), A6 D24 (io), A7 GND (power) hidden to GND, A8 D29 (io), A9 GND (power) hidden to GND, A11 GND (power) hidden to GND, A15 IGNEE (in), A16 INTR (in), A17 AHOLD (in), B1 D19 (io), B2 D21 (io), B3 GND (power) hidden to GND, B4 GND (power) hidden to GND, B5 GND (power) hidden to GND, B6 D25 (io), B7 VCC (power) hidden to VCC, B8 D31 (io), B9 VCC (power) hidden to VCC, B11 VCC (power) hidden to VCC, B15 NMI (in), B17 EADS (in), C1 D11 (io), C2 D18 (io), C3 CLK (in), C4 VCC (power) hidden to VCC, C5 VCC (power) hidden to VCC, C6 D27 (io), C7 D26 (io), C8 D28 (io), C9 D30 (io), C14 FERR (out), C15 FLUSH (in), C16 RESET (in), C17 BS16 (in), D1 D9 (io), D2 D13 (io), D3 D17 (io), D15 A20M (in), D16 BS8 (in), D17 BOFF (in), E1 GND (power) hidden to GND, E2 VCC (power) hidden to VCC, E3 D10 (io), E15 HOLD (in), E16 VCC (power) hidden to VCC, E17 GND (power) hidden to GND, F1 DP1 (io), F2 D8 (io), F3 D15 (io), F15 KEN (in), F16 RDY (in), F17 BE3 (hiz), G1 GND (power) hidden to GND, G2 VCC (power) hidden to VCC, G3 D12 (io), G16 VCC (power) hidden to VCC, G17 GND (power) hidden to GND, H1 GND (power) hidden to GND, H2 D3 (io), H3 DP2 (io), H15 BRDY (in), H16 VCC (power) hidden to VCC, H17 GND (power) hidden to GND, J1 VCC (power) hidden to VCC, J2 D5 (io), J3 D16 (io), J15 BE2 (hiz), J16 BE1 (hiz), J17 PCD (hiz), K1 GND (power) hidden to GND, K2 VCC (power) hidden to VCC, K3 D14 (io), K15 BE0 (hiz), K16 VCC (power) hidden to VCC, K17 GND (power) hidden to GND, L1 GND (power) hidden to GND, L2 D6 (io), L3 D7 (io), L15 PWT (hiz), L16 VCC (power) hidden to VCC, M1 GND (power) hidden to GND, M2 VCC (power) hidden to VCC, M3 D4 (io), M15 D/-C (hiz), M16 VCC (power) hidden to VCC, M17 GND (power) hidden to GND, N1 D2 (io), N2 D1 (io), N3 DP0 (io), N15 LOCK (hiz), N16 M/-IO (hiz), N17 W/-R (hiz), P1 D0 (io), P2 A29 (io), P3 A30 (io), P15 HLDA (out), P16 VCC (power) hidden to VCC, P17 GND (power) hidden to GND, Q1 A31 (io), Q2 GND (power) hidden to GND, Q3 A17 (io), Q4 A19 (io), Q5 A21 (io), Q6 A24 (io), Q7 A22 (io), Q8 A20 (io), Q9 A16 (io), Q10 A13 (io), Q11 A9 (io), Q12 A5 (io), Q13 A7 (io), Q14 A2 (io), Q15 BREQ (out), Q16 PLOCK (hiz), Q17 PCHK (hiz), R1 A28 (io), R2 A25 (io), R3 VCC (power) hidden to VCC, R4 GND (power) hidden to GND, R5 A18 (io), R6 VCC (power) hidden to VCC, R7 A15 (io), R8 VCC (power) hidden to VCC, R9 VCC (power) hidden to VCC, R10 VCC (power) hidden to VCC, R11 VCC (power) hidden to VCC, R12 A11 (io), R13 A8 (io), R14 VCC (power) hidden to VCC, R15 A3 (io), R16 BLAST (hiz), S1 A27 (io), S2 A26 (io), S3 A23 (io), S5 A14 (io), S6 GND (power) hidden to GND, S7 A12 (io), S8 GND (power) hidden to GND, S9 GND (power) hidden to GND, S10 GND (power) hidden to GND, S11 GND (power) hidden to GND, S12 GND (power) hidden to GND, S13 A10 (io), S14 GND (power) hidden to GND, S15 A6 (io), S16 A4 (io), S17 ADS (hiz)


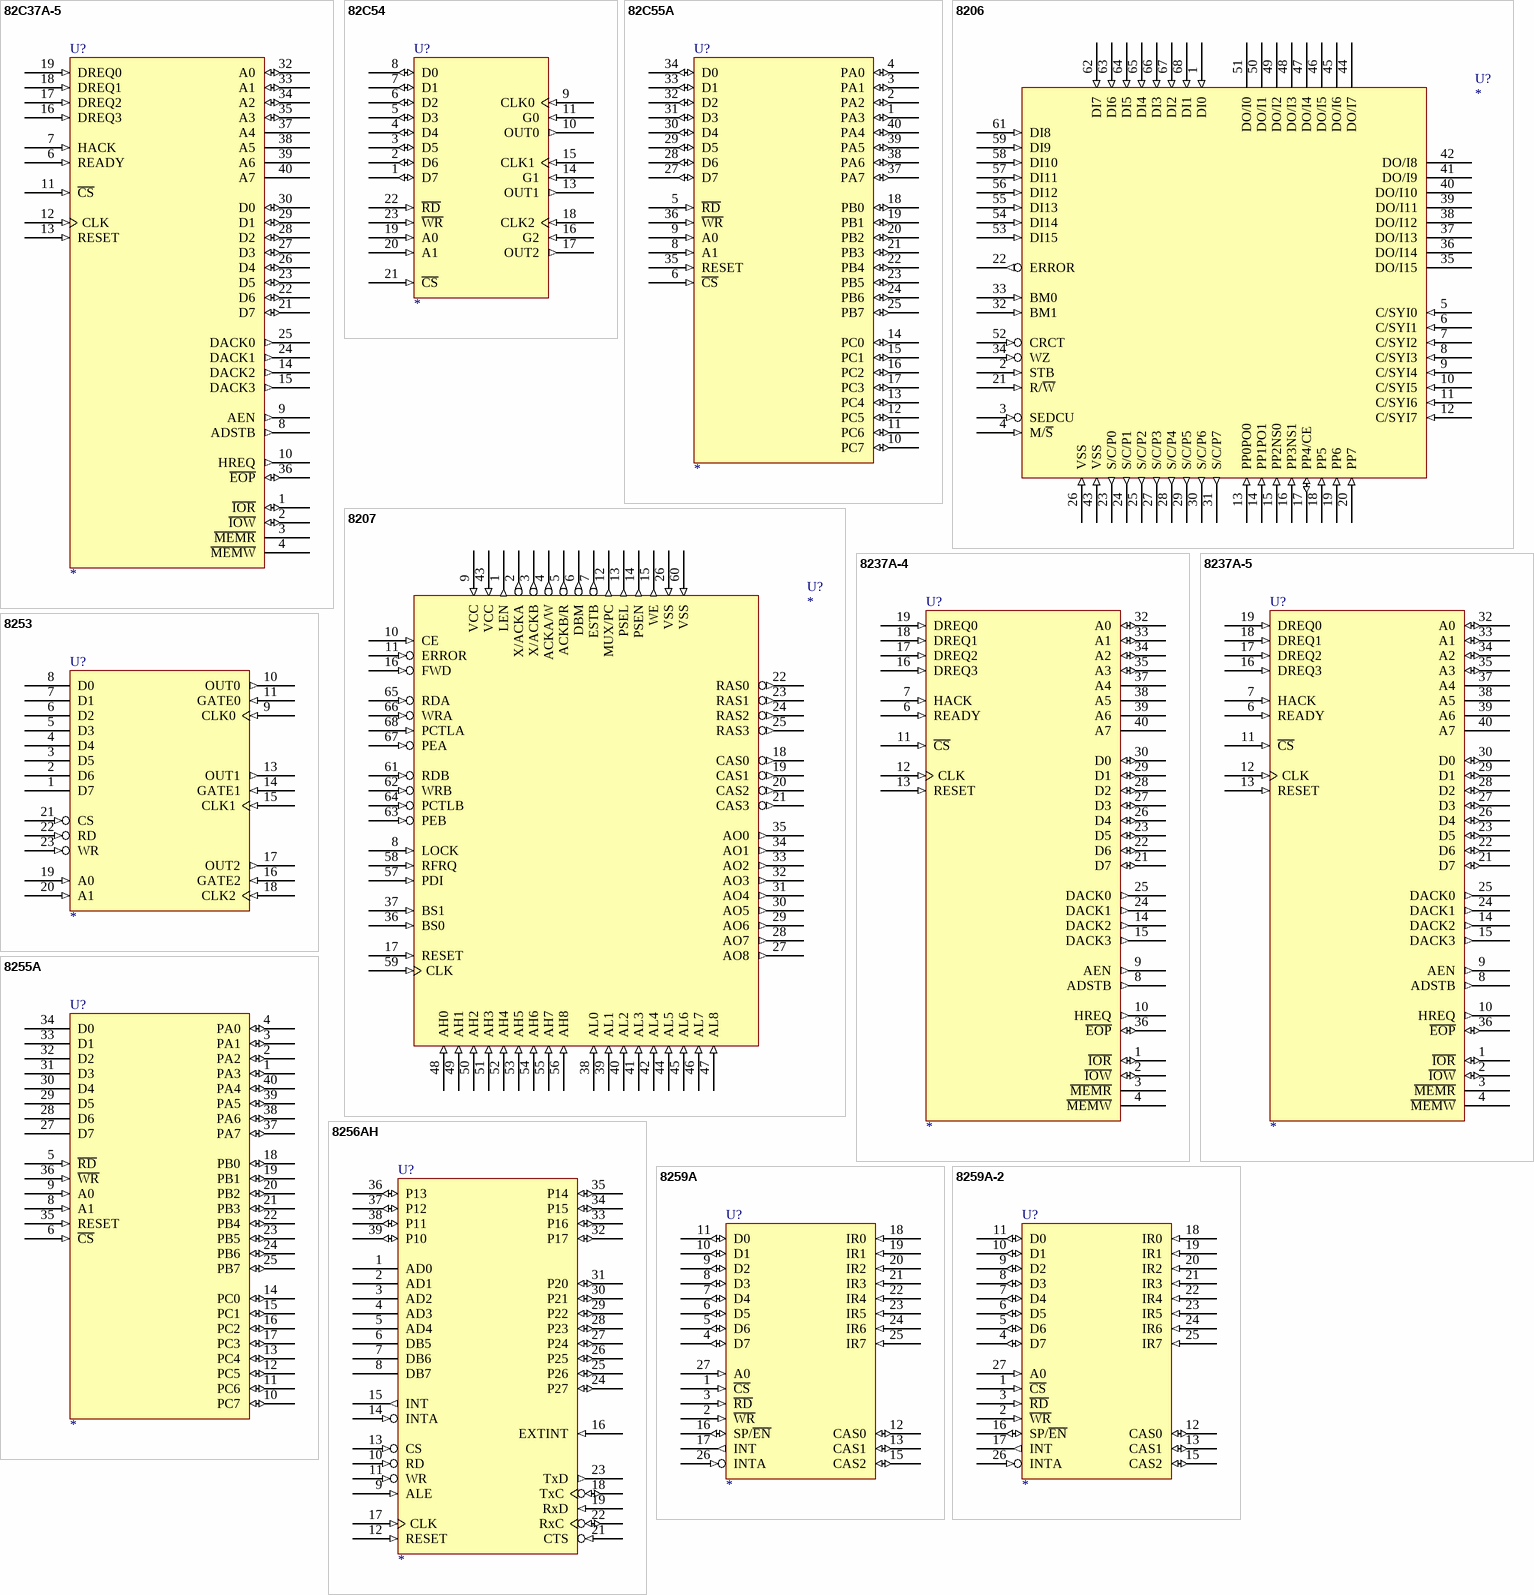
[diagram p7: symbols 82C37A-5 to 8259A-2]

## 82C37A-5
designator U?
pins: 1 ~{IOR} (io), 2 ~{IOW} (io), 3 ~{MEMR} (hiz), 4 ~{MEMW} (hiz), 5 VCC (power) hidden to VCC, 6 READY (in), 7 HACK (in), 8 ADSTB (out), 9 AEN (out), 10 HREQ (out), 11 ~{CS} (in), 12 CLK (in), 13 RESET (in), 14 DACK2 (out), 15 DACK3 (out), 16 DREQ3 (in), 17 DREQ2 (in), 18 DREQ1 (in), 19 DREQ0 (in), 20 VSS (power) hidden to VSS, 21 D7 (io), 22 D6 (io), 23 D5 (io), 24 DACK1 (out), 25 DACK0 (out), 26 D4 (io), 27 D3 (io), 28 D2 (io), 29 D1 (io), 30 D0 (io), 31 VCC (power) hidden to VCC, 32 A0 (io), 33 A1 (io), 34 A2 (io), 35 A3 (io), 36 ~{EOP} (io), 37 A4 (hiz), 38 A5 (hiz), 39 A6 (hiz), 40 A7 (hiz)

## 82C54
designator U?
pins: 1 D7 (io), 2 D6 (io), 3 D5 (io), 4 D4 (io), 5 D3 (io), 6 D2 (io), 7 D1 (io), 8 D0 (io), 9 CLK0 (in), 10 OUT0 (out), 11 G0 (in), 12 GND (power) hidden to GND, 13 OUT1 (out), 14 G1 (in), 15 CLK1 (in), 16 G2 (in), 17 OUT2 (out), 18 CLK2 (in), 19 A0 (in), 20 A1 (in), 21 ~{CS} (in), 22 ~{RD} (in), 23 ~{WR} (in), 24 VCC (power) hidden to VCC

## 82C55A
designator U?
pins: 1 PA3 (io), 2 PA2 (io), 3 PA1 (io), 4 PA0 (io), 5 ~{RD} (in), 6 ~{CS} (in), 7 GND (power) hidden to GND, 8 A1 (in), 9 A0 (in), 10 PC7 (io), 11 PC6 (io), 12 PC5 (io), 13 PC4 (io), 14 PC0 (io), 15 PC1 (io), 16 PC2 (io), 17 PC3 (io), 18 PB0 (io), 19 PB1 (io), 20 PB2 (io), 21 PB3 (io), 22 PB4 (io), 23 PB5 (io), 24 PB6 (io), 25 PB7 (io), 26 VCC (power) hidden to VCC, 27 D7 (io), 28 D6 (io), 29 D5 (io), 30 D4 (io), 31 D3 (io), 32 D2 (io), 33 D1 (io), 34 D0 (io), 35 RESET (in), 36 ~{WR} (in), 37 PA7 (io), 38 PA6 (io), 39 PA5 (io), 40 PA4 (io)

## 8206
designator U?
footprint JEDECA-68
pins: 1 DI0 (in), 2 STB (in), 3 SEDCU (in), 4 M/~{S} (in), 5 C/SYI0 (in), 6 C/SYI1 (in), 7 C/SYI2 (in), 8 C/SYI3 (in), 9 C/SYI4 (in), 10 C/SYI5 (in), 11 C/SYI6 (in), 12 C/SYI7 (in), 13 PP0PO0 (in), 14 PP1PO1 (in), 15 PP2NS0 (in), 16 PP3NS1 (in), 17 PP4/CE (io), 18 PP5 (in), 19 PP6 (in), 20 PP7 (in), 21 R/~{W} (in), 22 ERROR (out), 23 S/C/P0 (out), 24 S/C/P1 (out), 25 S/C/P2 (out), 26 VSS (in), 27 S/C/P3 (out), 28 S/C/P4 (out), 29 S/C/P5 (out), 30 S/C/P6 (out), 31 S/C/P7 (out), 32 BM1 (in), 33 BM0 (in), 34 WZ (in), 35 DO/I15 (hiz), 36 DO/I14 (hiz), 37 DO/I13 (hiz), 38 DO/I12 (hiz), 39 DO/I11 (hiz), 40 DO/I10 (hiz), 41 DO/I9 (hiz), 42 DO/I8 (hiz), 43 VSS (in), 44 DO/I7 (hiz), 45 DO/I6 (hiz), 46 DO/I5 (hiz), 47 DO/I4 (hiz), 48 DO/I3 (hiz), 49 DO/I2 (hiz), 50 DO/I1 (hiz), 51 DO/I0 (hiz), 52 CRCT (in), 53 DI15 (in), 54 DI14 (in), 55 DI13 (in), 56 DI12 (in), 57 DI11 (in), 58 DI10 (in), 59 DI9 (in), 60 VCC (power) hidden to VCC, 61 DI8 (in), 62 DI7 (in), 63 DI6 (in), 64 DI5 (in), 65 DI4 (in), 66 DI3 (in), 67 DI2 (in), 68 DI1 (in)

## 8207
designator U?
footprint JEDECA-68
pins: 1 LEN (out), 2 X/ACKA (out), 3 X/ACKB (out), 4 ACKA/W (out), 5 ACKB/R (out), 6 DBM (out), 7 ESTB (out), 8 LOCK (in), 9 VCC (in), 10 CE (in), 11 ERROR (in), 12 MUX/PC (out), 13 PSEL (out), 14 PSEN (out), 15 WE (out), 16 FWD (in), 17 RESET (in), 18 CAS0 (out), 19 CAS1 (out), 20 CAS2 (out), 21 CAS3 (out), 22 RAS0 (out), 23 RAS1 (out), 24 RAS2 (out), 25 RAS3 (out), 26 VSS (in), 27 AO8 (out), 28 AO7 (out), 29 AO6 (out), 30 AO5 (out), 31 AO4 (out), 32 AO3 (out), 33 AO2 (out), 34 AO1 (out), 35 AO0 (out), 36 BS0 (in), 37 BS1 (in), 38 AL0 (in), 39 AL1 (in), 40 AL2 (in), 41 AL3 (in), 42 AL4 (in), 43 VCC (in), 44 AL5 (in), 45 AL6 (in), 46 AL7 (in), 47 AL8 (in), 48 AH0 (in), 49 AH1 (in), 50 AH2 (in), 51 AH3 (in), 52 AH4 (in), 53 AH5 (in), 54 AH6 (in), 55 AH7 (in), 56 AH8 (in), 57 PDI (in), 58 RFRQ (in), 59 CLK (in), 60 VSS (in), 61 RDB (in), 62 WRB (in), 63 PEB (in), 64 PCTLB (in), 65 RDA (in), 66 WRA (in), 67 PEA (in), 68 PCTLA (in)

## 8237A-4
designator U?
pins: 1 ~{IOR} (io), 2 ~{IOW} (io), 3 ~{MEMR} (hiz), 4 ~{MEMW} (hiz), 5 VCC (power) hidden to VCC, 6 READY (in), 7 HACK (in), 8 ADSTB (out), 9 AEN (out), 10 HREQ (out), 11 ~{CS} (in), 12 CLK (in), 13 RESET (in), 14 DACK2 (out), 15 DACK3 (out), 16 DREQ3 (in), 17 DREQ2 (in), 18 DREQ1 (in), 19 DREQ0 (in), 20 VSS (power) hidden to VSS, 21 D7 (io), 22 D6 (io), 23 D5 (io), 24 DACK1 (out), 25 DACK0 (out), 26 D4 (io), 27 D3 (io), 28 D2 (io), 29 D1 (io), 30 D0 (io), 31 VCC (power) hidden to VCC, 32 A0 (io), 33 A1 (io), 34 A2 (io), 35 A3 (io), 36 ~{EOP} (io), 37 A4 (hiz), 38 A5 (hiz), 39 A6 (hiz), 40 A7 (hiz)

## 8237A-5
designator U?
pins: 1 ~{IOR} (io), 2 ~{IOW} (io), 3 ~{MEMR} (hiz), 4 ~{MEMW} (hiz), 5 VCC (power) hidden to VCC, 6 READY (in), 7 HACK (in), 8 ADSTB (out), 9 AEN (out), 10 HREQ (out), 11 ~{CS} (in), 12 CLK (in), 13 RESET (in), 14 DACK2 (out), 15 DACK3 (out), 16 DREQ3 (in), 17 DREQ2 (in), 18 DREQ1 (in), 19 DREQ0 (in), 20 VSS (power) hidden to VSS, 21 D7 (io), 22 D6 (io), 23 D5 (io), 24 DACK1 (out), 25 DACK0 (out), 26 D4 (io), 27 D3 (io), 28 D2 (io), 29 D1 (io), 30 D0 (io), 31 VCC (power) hidden to VCC, 32 A0 (io), 33 A1 (io), 34 A2 (io), 35 A3 (io), 36 ~{EOP} (io), 37 A4 (hiz), 38 A5 (hiz), 39 A6 (hiz), 40 A7 (hiz)

## 8253
designator U?
footprint DIP-24
pins: 1 D7 (hiz), 2 D6 (hiz), 3 D5 (hiz), 4 D4 (hiz), 5 D3 (hiz), 6 D2 (hiz), 7 D1 (hiz), 8 D0 (hiz), 9 CLK0 (in), 10 OUT0 (out), 11 GATE0 (in), 12 GND (power) hidden to GND, 13 OUT1 (out), 14 GATE1 (in), 15 CLK1 (in), 16 GATE2 (in), 17 OUT2 (out), 18 CLK2 (in), 19 A0 (in), 20 A1 (in), 21 CS (in), 22 RD (in), 23 WR (in), 24 VCC (power) hidden to VCC

## 8255A
designator U?
footprint DIP-40
pins: 1 PA3 (io), 2 PA2 (io), 3 PA1 (io), 4 PA0 (io), 5 ~{RD} (in), 6 ~{CS} (in), 7 GND (power) hidden to GND, 8 A1 (in), 9 A0 (in), 10 PC7 (io), 11 PC6 (io), 12 PC5 (io), 13 PC4 (io), 14 PC0 (io), 15 PC1 (io), 16 PC2 (io), 17 PC3 (io), 18 PB0 (io), 19 PB1 (io), 20 PB2 (io), 21 PB3 (io), 22 PB4 (io), 23 PB5 (io), 24 PB6 (io), 25 PB7 (io), 26 VCC (power) hidden to VCC, 27 D7 (hiz), 28 D6 (hiz), 29 D5 (hiz), 30 D4 (hiz), 31 D3 (hiz), 32 D2 (hiz), 33 D1 (hiz), 34 D0 (hiz), 35 RESET (in), 36 ~{WR} (in), 37 PA7 (io), 38 PA6 (io), 39 PA5 (io), 40 PA4 (io)

## 8256AH
designator U?
footprint DIP-40
pins: 1 AD0 (hiz), 2 AD1 (hiz), 3 AD2 (hiz), 4 AD3 (hiz), 5 AD4 (hiz), 6 DB5 (hiz), 7 DB6 (hiz), 8 DB7 (hiz), 9 ALE (in), 10 RD (in), 11 WR (in), 12 RESET (in), 13 CS (in), 14 INTA (in), 15 INT (out), 16 EXTINT (in), 17 CLK (in), 18 TxC (io), 19 RxD (in), 20 GND (power) hidden to GND, 21 CTS (in), 22 RxC (io), 23 TxD (out), 24 P27 (io), 25 P26 (io), 26 P25 (io), 27 P24 (io), 28 P23 (io), 29 P22 (io), 30 P21 (io), 31 P20 (io), 32 P17 (io), 33 P16 (io), 34 P15 (io), 35 P14 (io), 36 P13 (io), 37 P12 (io), 38 P11 (io), 39 P10 (io), 40 VCC (power) hidden to VCC

## 8259A
designator U?
pins: 1 ~{CS} (in), 2 ~{WR} (in), 3 ~{RD} (in), 4 D7 (io), 5 D6 (io), 6 D5 (io), 7 D4 (io), 8 D3 (io), 9 D2 (io), 10 D1 (io), 11 D0 (io), 12 CAS0 (io), 13 CAS1 (io), 14 GND (power) hidden to GND, 15 CAS2 (io), 16 SP/~{EN} (io), 17 INT (out), 18 IR0 (in), 19 IR1 (in), 20 IR2 (in), 21 IR3 (in), 22 IR4 (in), 23 IR5 (in), 24 IR6 (in), 25 IR7 (in), 26 INTA (in), 27 A0 (in), 28 VCC (power) hidden to VCC

## 8259A-2
designator U?
pins: 1 ~{CS} (in), 2 ~{WR} (in), 3 ~{RD} (in), 4 D7 (io), 5 D6 (io), 6 D5 (io), 7 D4 (io), 8 D3 (io), 9 D2 (io), 10 D1 (io), 11 D0 (io), 12 CAS0 (io), 13 CAS1 (io), 14 GND (power) hidden to GND, 15 CAS2 (io), 16 SP/~{EN} (io), 17 INT (out), 18 IR0 (in), 19 IR1 (in), 20 IR2 (in), 21 IR3 (in), 22 IR4 (in), 23 IR5 (in), 24 IR6 (in), 25 IR7 (in), 26 INTA (in), 27 A0 (in), 28 VCC (power) hidden to VCC

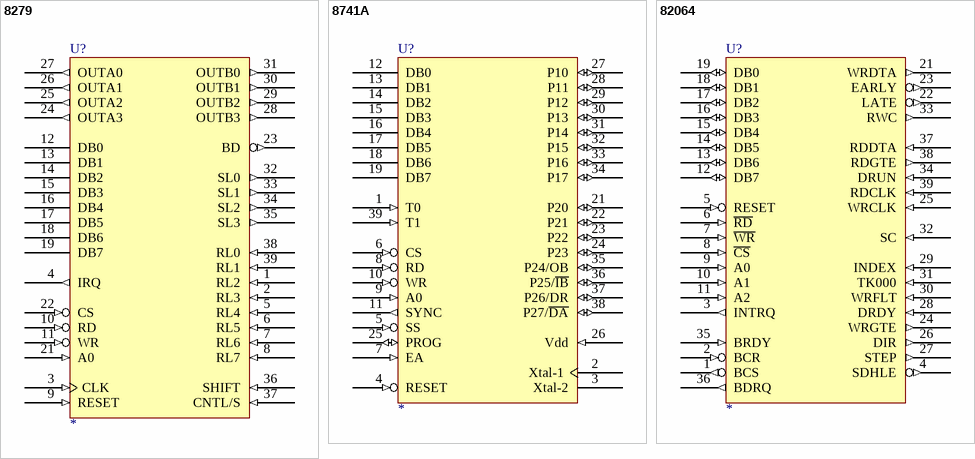
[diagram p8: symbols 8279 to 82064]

## 8279
designator U?
footprint DIP-40
pins: 1 RL2 (in), 2 RL3 (in), 3 CLK (in), 4 IRQ (out), 5 RL4 (in), 6 RL5 (in), 7 RL6 (in), 8 RL7 (in), 9 RESET (in), 10 RD (in), 11 WR (in), 12 DB0 (hiz), 13 DB1 (hiz), 14 DB2 (hiz), 15 DB3 (hiz), 16 DB4 (hiz), 17 DB5 (hiz), 18 DB6 (hiz), 19 DB7 (hiz), 20 GND (power) hidden to GND, 21 A0 (in), 22 CS (in), 23 BD (out), 24 OUTA3 (out), 25 OUTA2 (out), 26 OUTA1 (out), 27 OUTA0 (out), 28 OUTB3 (out), 29 OUTB2 (out), 30 OUTB1 (out), 31 OUTB0 (out), 32 SL0 (out), 33 SL1 (out), 34 SL2 (out), 35 SL3 (out), 36 SHIFT (in), 37 CNTL/S (in), 38 RL0 (in), 39 RL1 (in), 40 VCC (power) hidden to VCC

## 8741A
designator U?
footprint DIP-40
pins: 1 T0 (in), 2 Xtal-1, 3 Xtal-2, 4 RESET (in), 5 SS (in), 6 CS (in), 7 EA (in), 8 RD (in), 9 A0 (in), 10 WR (in), 11 SYNC (out), 12 DB0 (hiz), 13 DB1 (hiz), 14 DB2 (hiz), 15 DB3 (hiz), 16 DB4 (hiz), 17 DB5 (hiz), 18 DB6 (hiz), 19 DB7 (hiz), 20 GND (power) hidden to GND, 21 P20 (io), 22 P21 (io), 23 P22 (io), 24 P23 (io), 25 PROG (io), 26 Vdd (in), 27 P10 (io), 28 P11 (io), 29 P12 (io), 30 P13 (io), 31 P14 (io), 32 P15 (io), 33 P16 (io), 34 P17 (io), 35 P24/OB (io), 36 P25/~{IB} (io), 37 P26/DR (io), 38 P27/~{DA} (io), 39 T1 (in), 40 VCC (power) hidden to VCC

## 82064
designator U?
pins: 1 BCS (out), 2 BCR (in), 3 INTRQ (out), 4 SDHLE (out), 5 RESET (in), 6 ~{RD} (in), 7 ~{WR} (in), 8 ~{CS} (in), 9 A0 (in), 10 A1 (in), 11 A2 (in), 12 DB7 (io), 13 DB6 (io), 14 DB5 (io), 15 DB4 (io), 16 DB3 (io), 17 DB2 (io), 18 DB1 (io), 19 DB0 (io), 20 GND (power) hidden to GND, 21 WRDTA (out), 22 LATE (out), 23 EARLY (out), 24 WRGTE (out), 25 WRCLK (in), 26 DIR (out), 27 STEP (out), 28 DRDY (in), 29 INDEX (in), 30 WRFLT (in), 31 TK000 (in), 32 SC (in), 33 RWC (out), 34 DRUN (in), 35 BRDY (in), 36 BDRQ (out), 37 RDDTA (in), 38 RDGTE (out), 39 RDCLK (in), 40 VCC (power) hidden to VCC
